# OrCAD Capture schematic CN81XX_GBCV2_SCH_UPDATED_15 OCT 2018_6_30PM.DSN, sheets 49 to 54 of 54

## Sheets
49 25.BOOT EMMC /SD: size Custom; title: BOOT EMMC/MMC
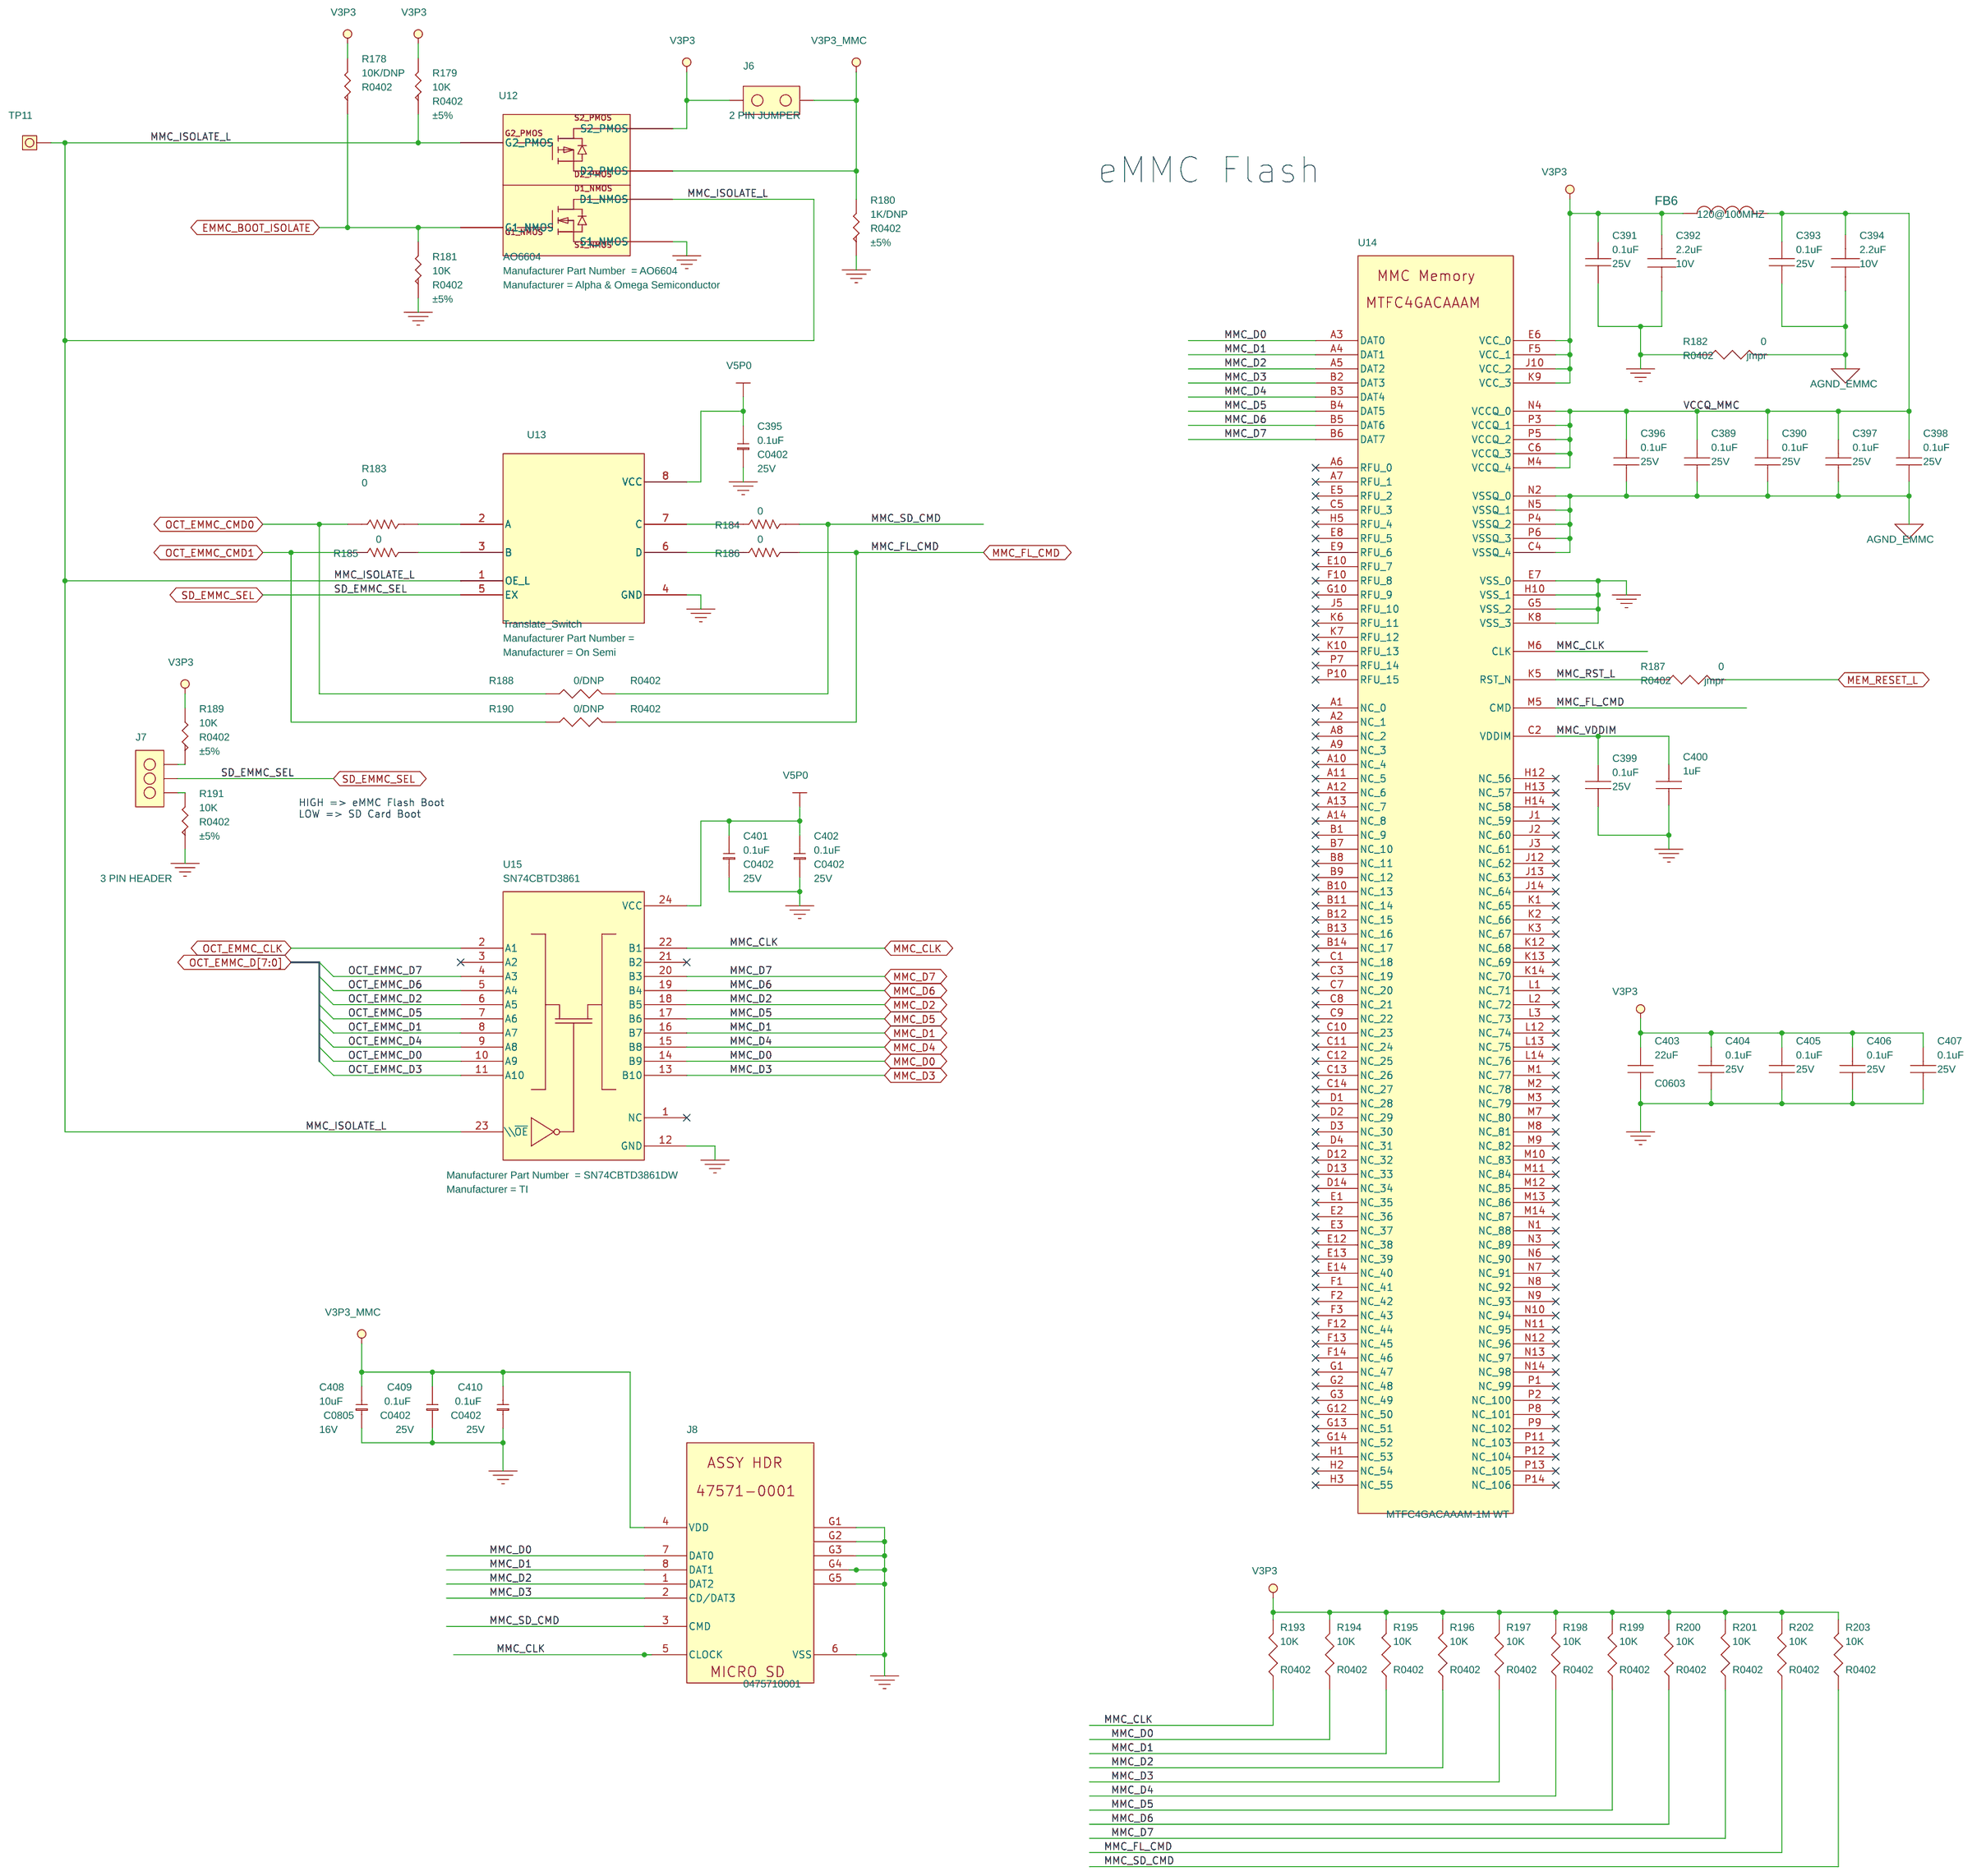
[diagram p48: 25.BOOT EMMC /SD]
50 10.CN81XX DLM3:0, RGMII: size B; title: CN81XX DLM3:0, RGMII
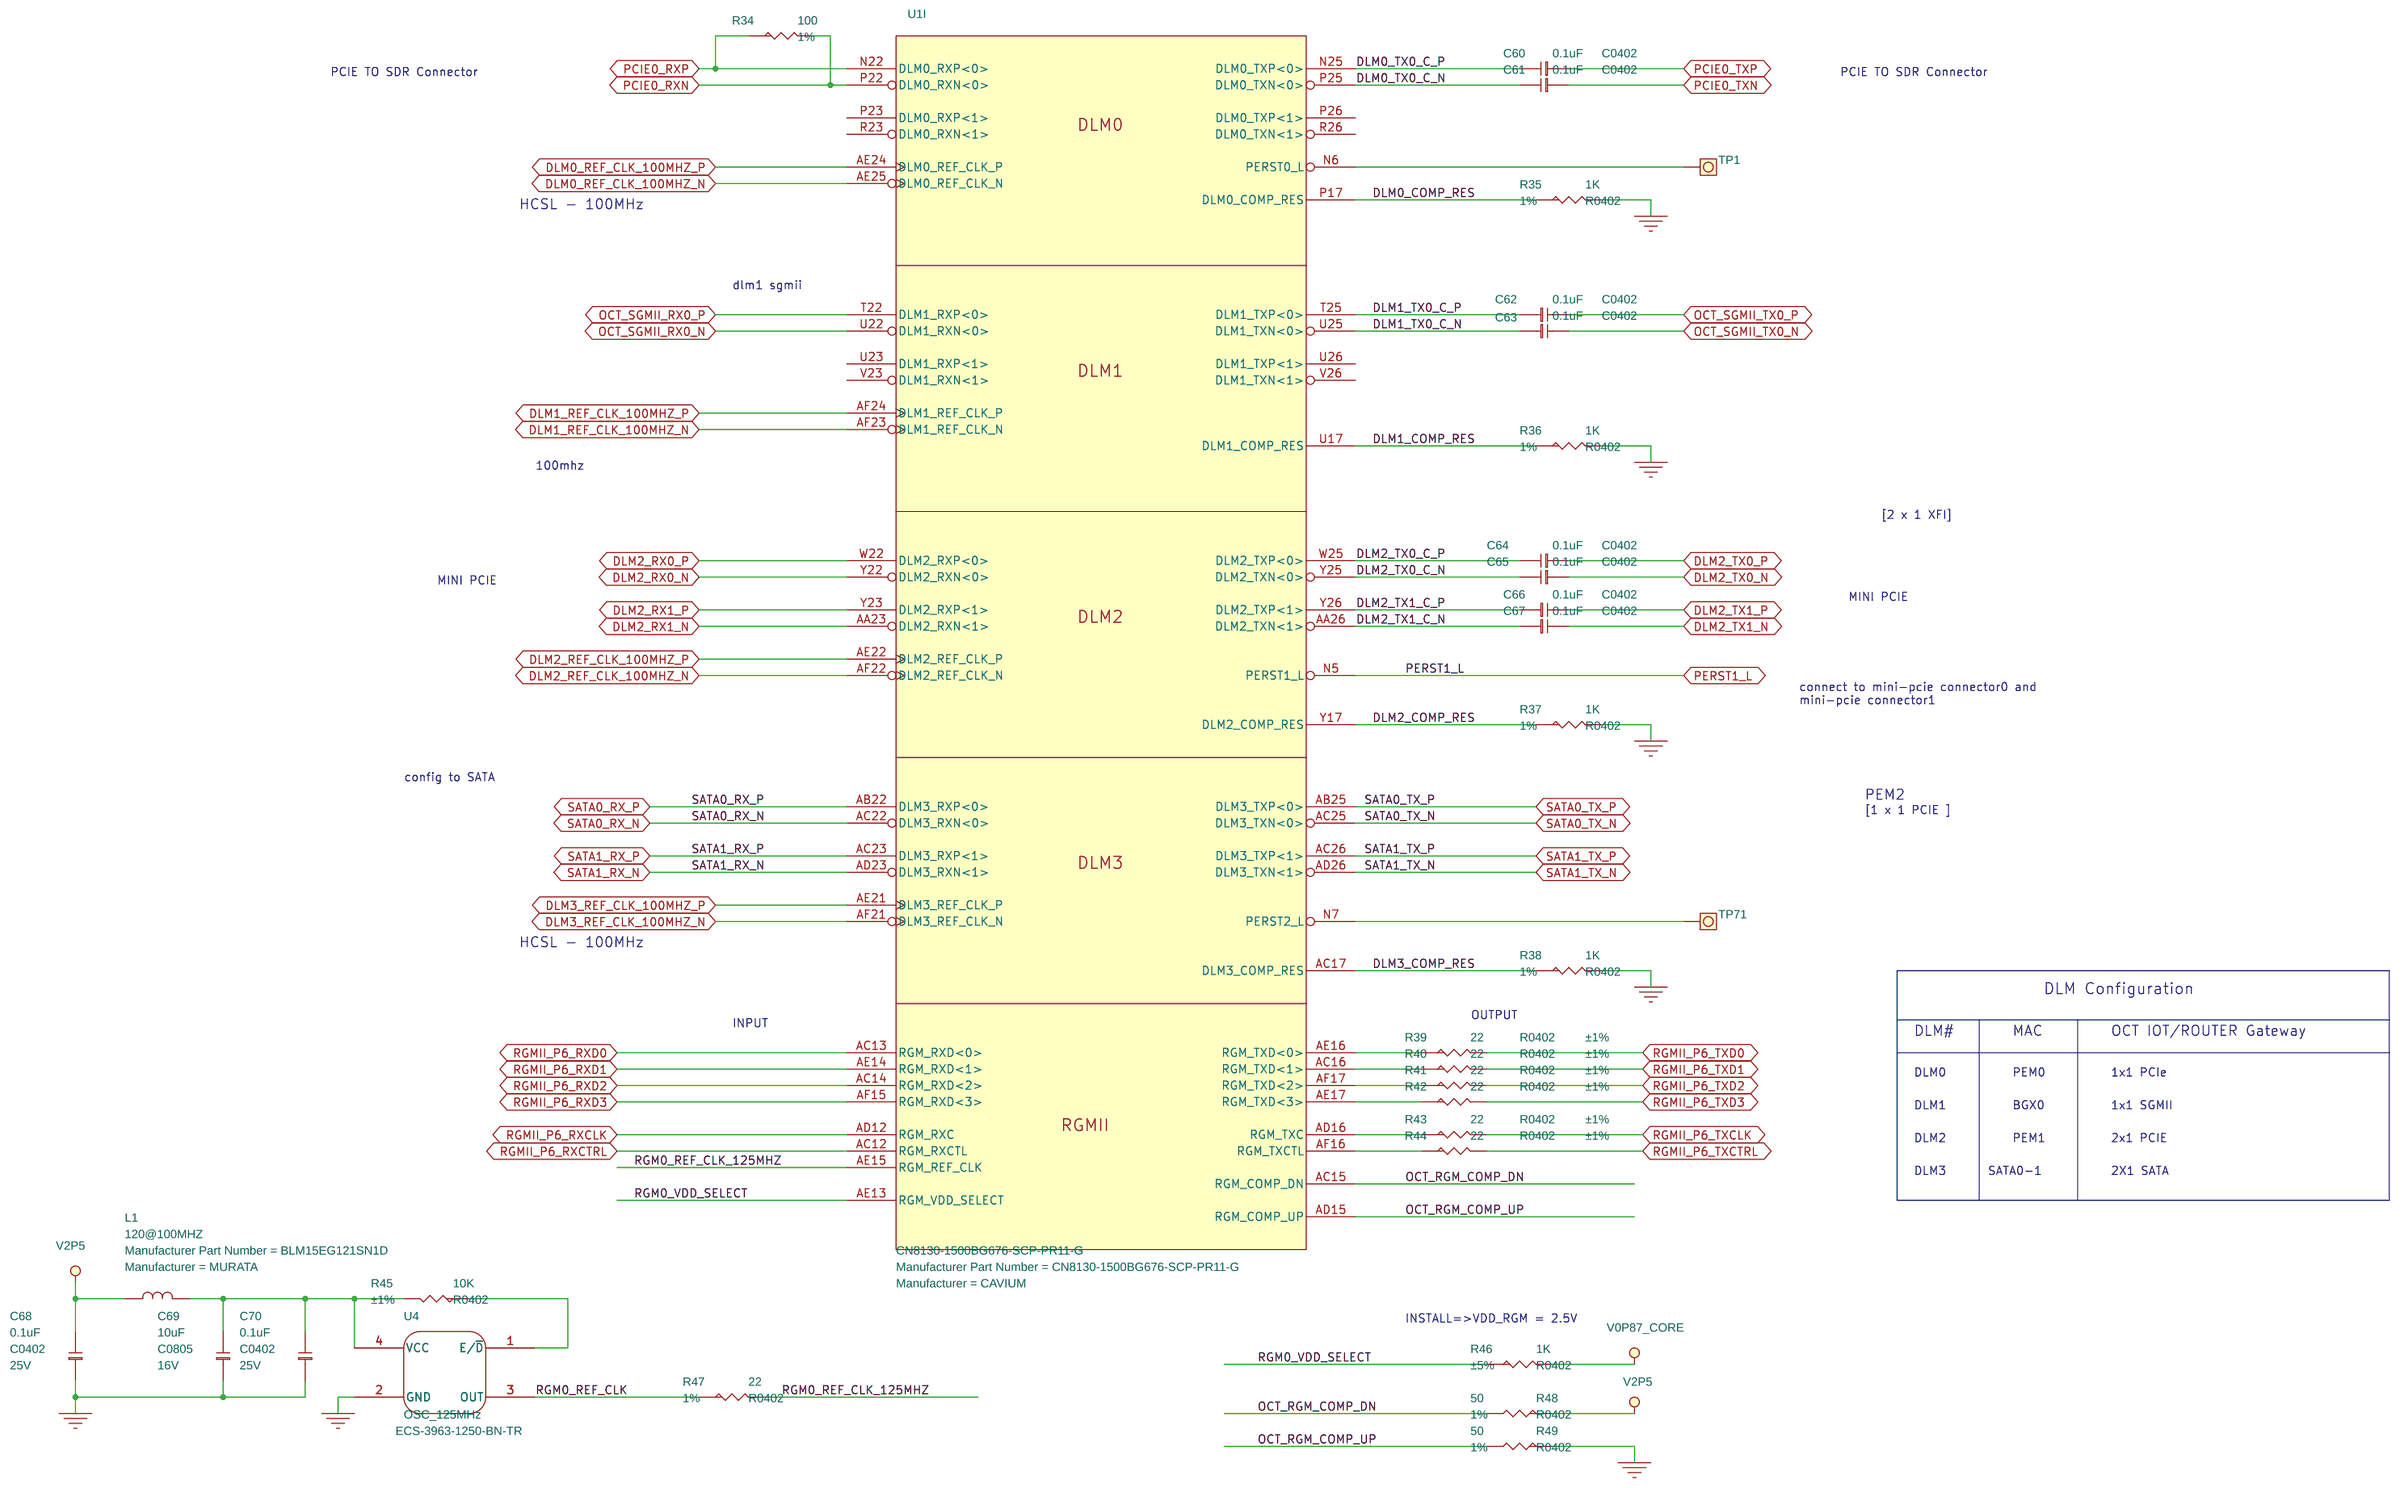
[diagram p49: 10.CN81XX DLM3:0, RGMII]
51 14.CN81XX I/O & MISC VDD: size B; title: CN81XX I/O & MISC VDD
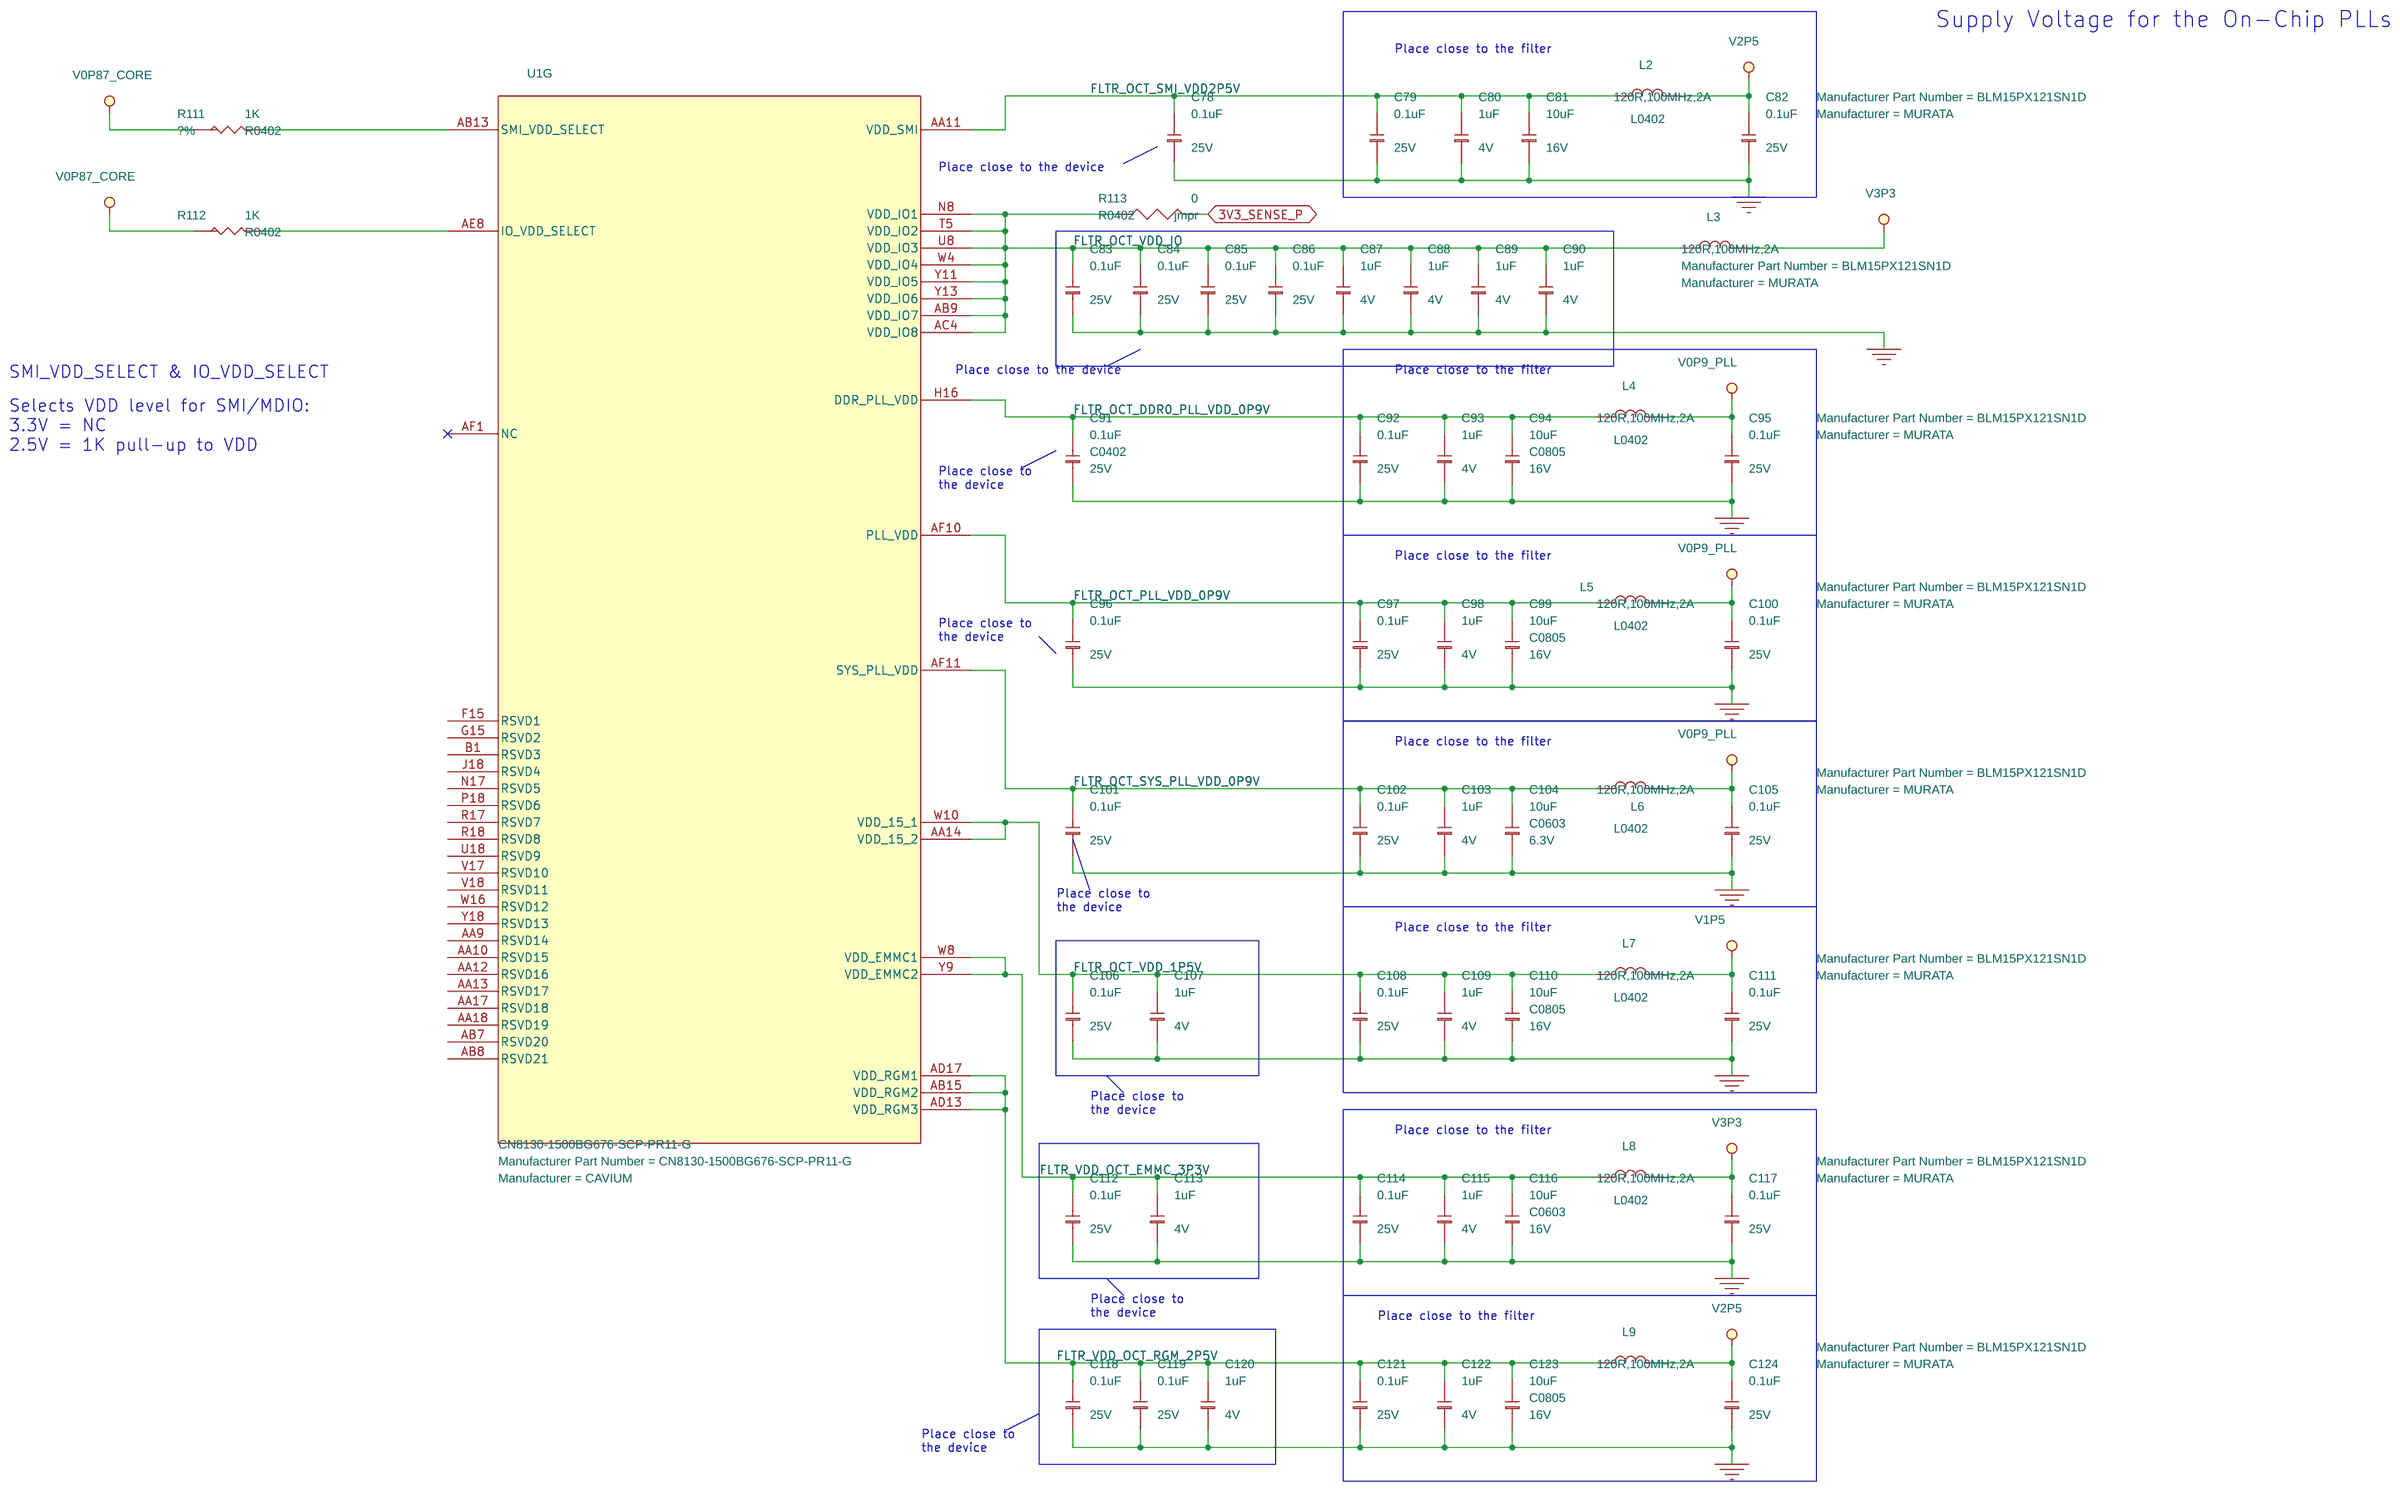
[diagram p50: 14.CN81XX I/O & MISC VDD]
52 31.CONTLR : CPU CORE & 3V3: size B; title: CONTROL:CPU  CORE&3V3
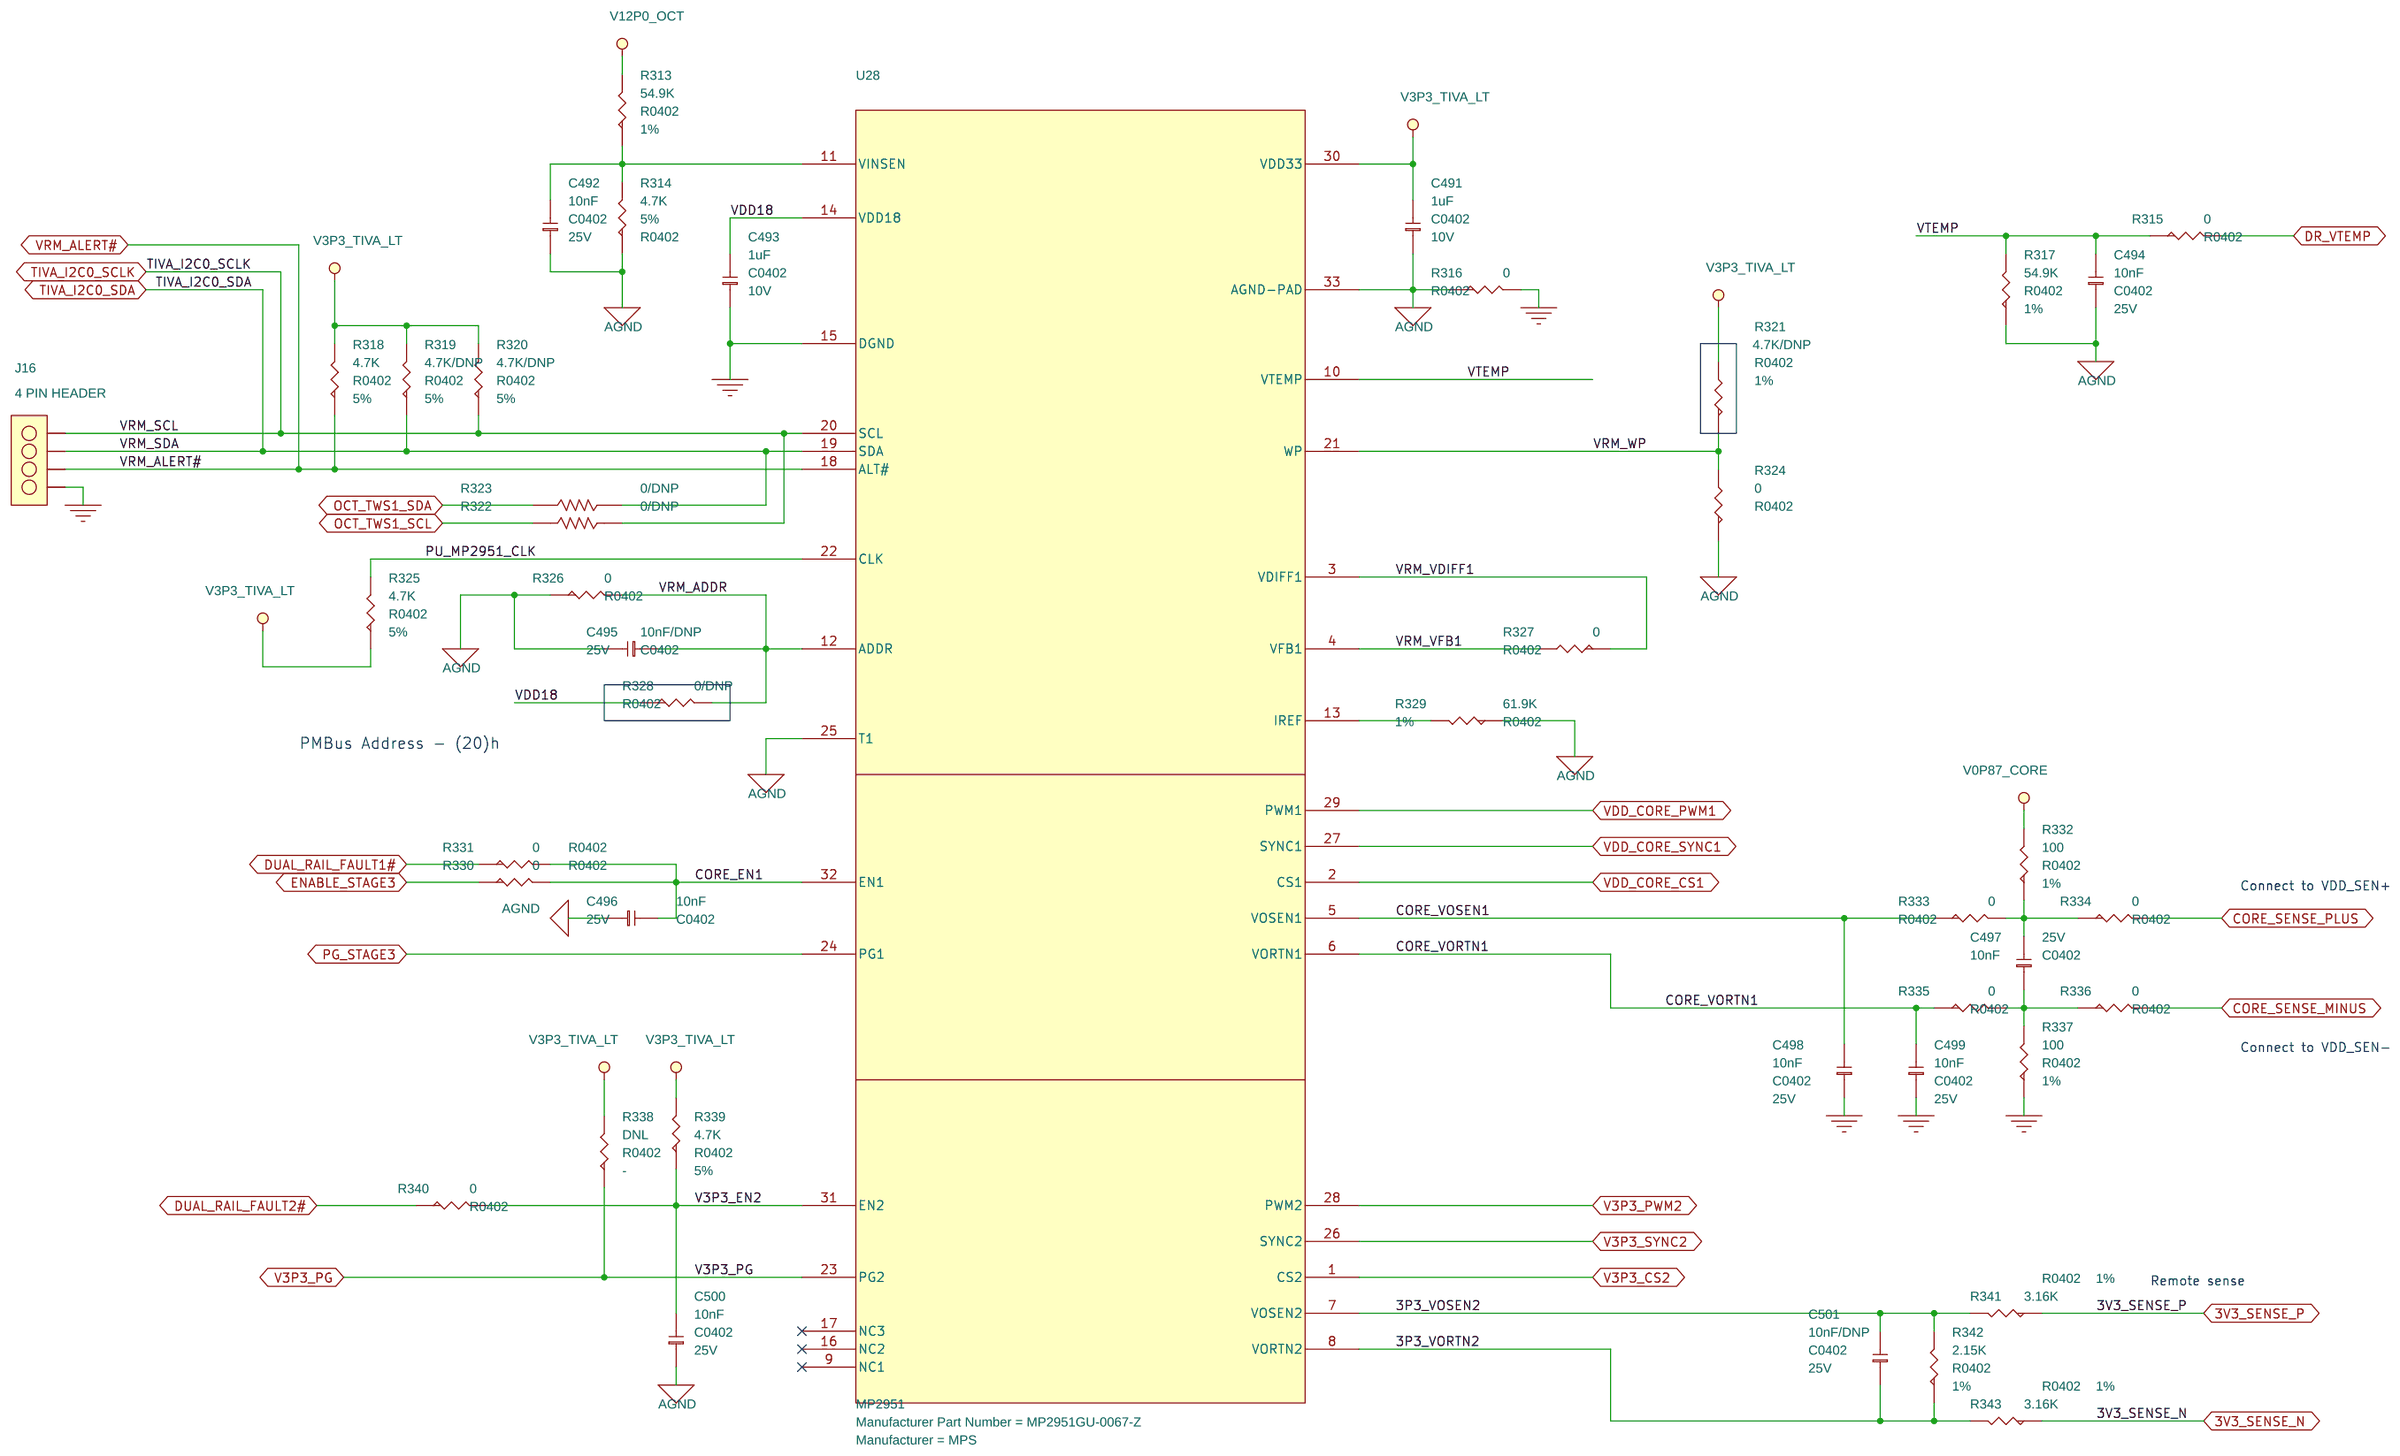
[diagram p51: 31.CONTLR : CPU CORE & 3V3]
53 12.CN81XX MISCELLANEOUS I/O: size B; title: CN81XX MISCELLANEOUS I/O
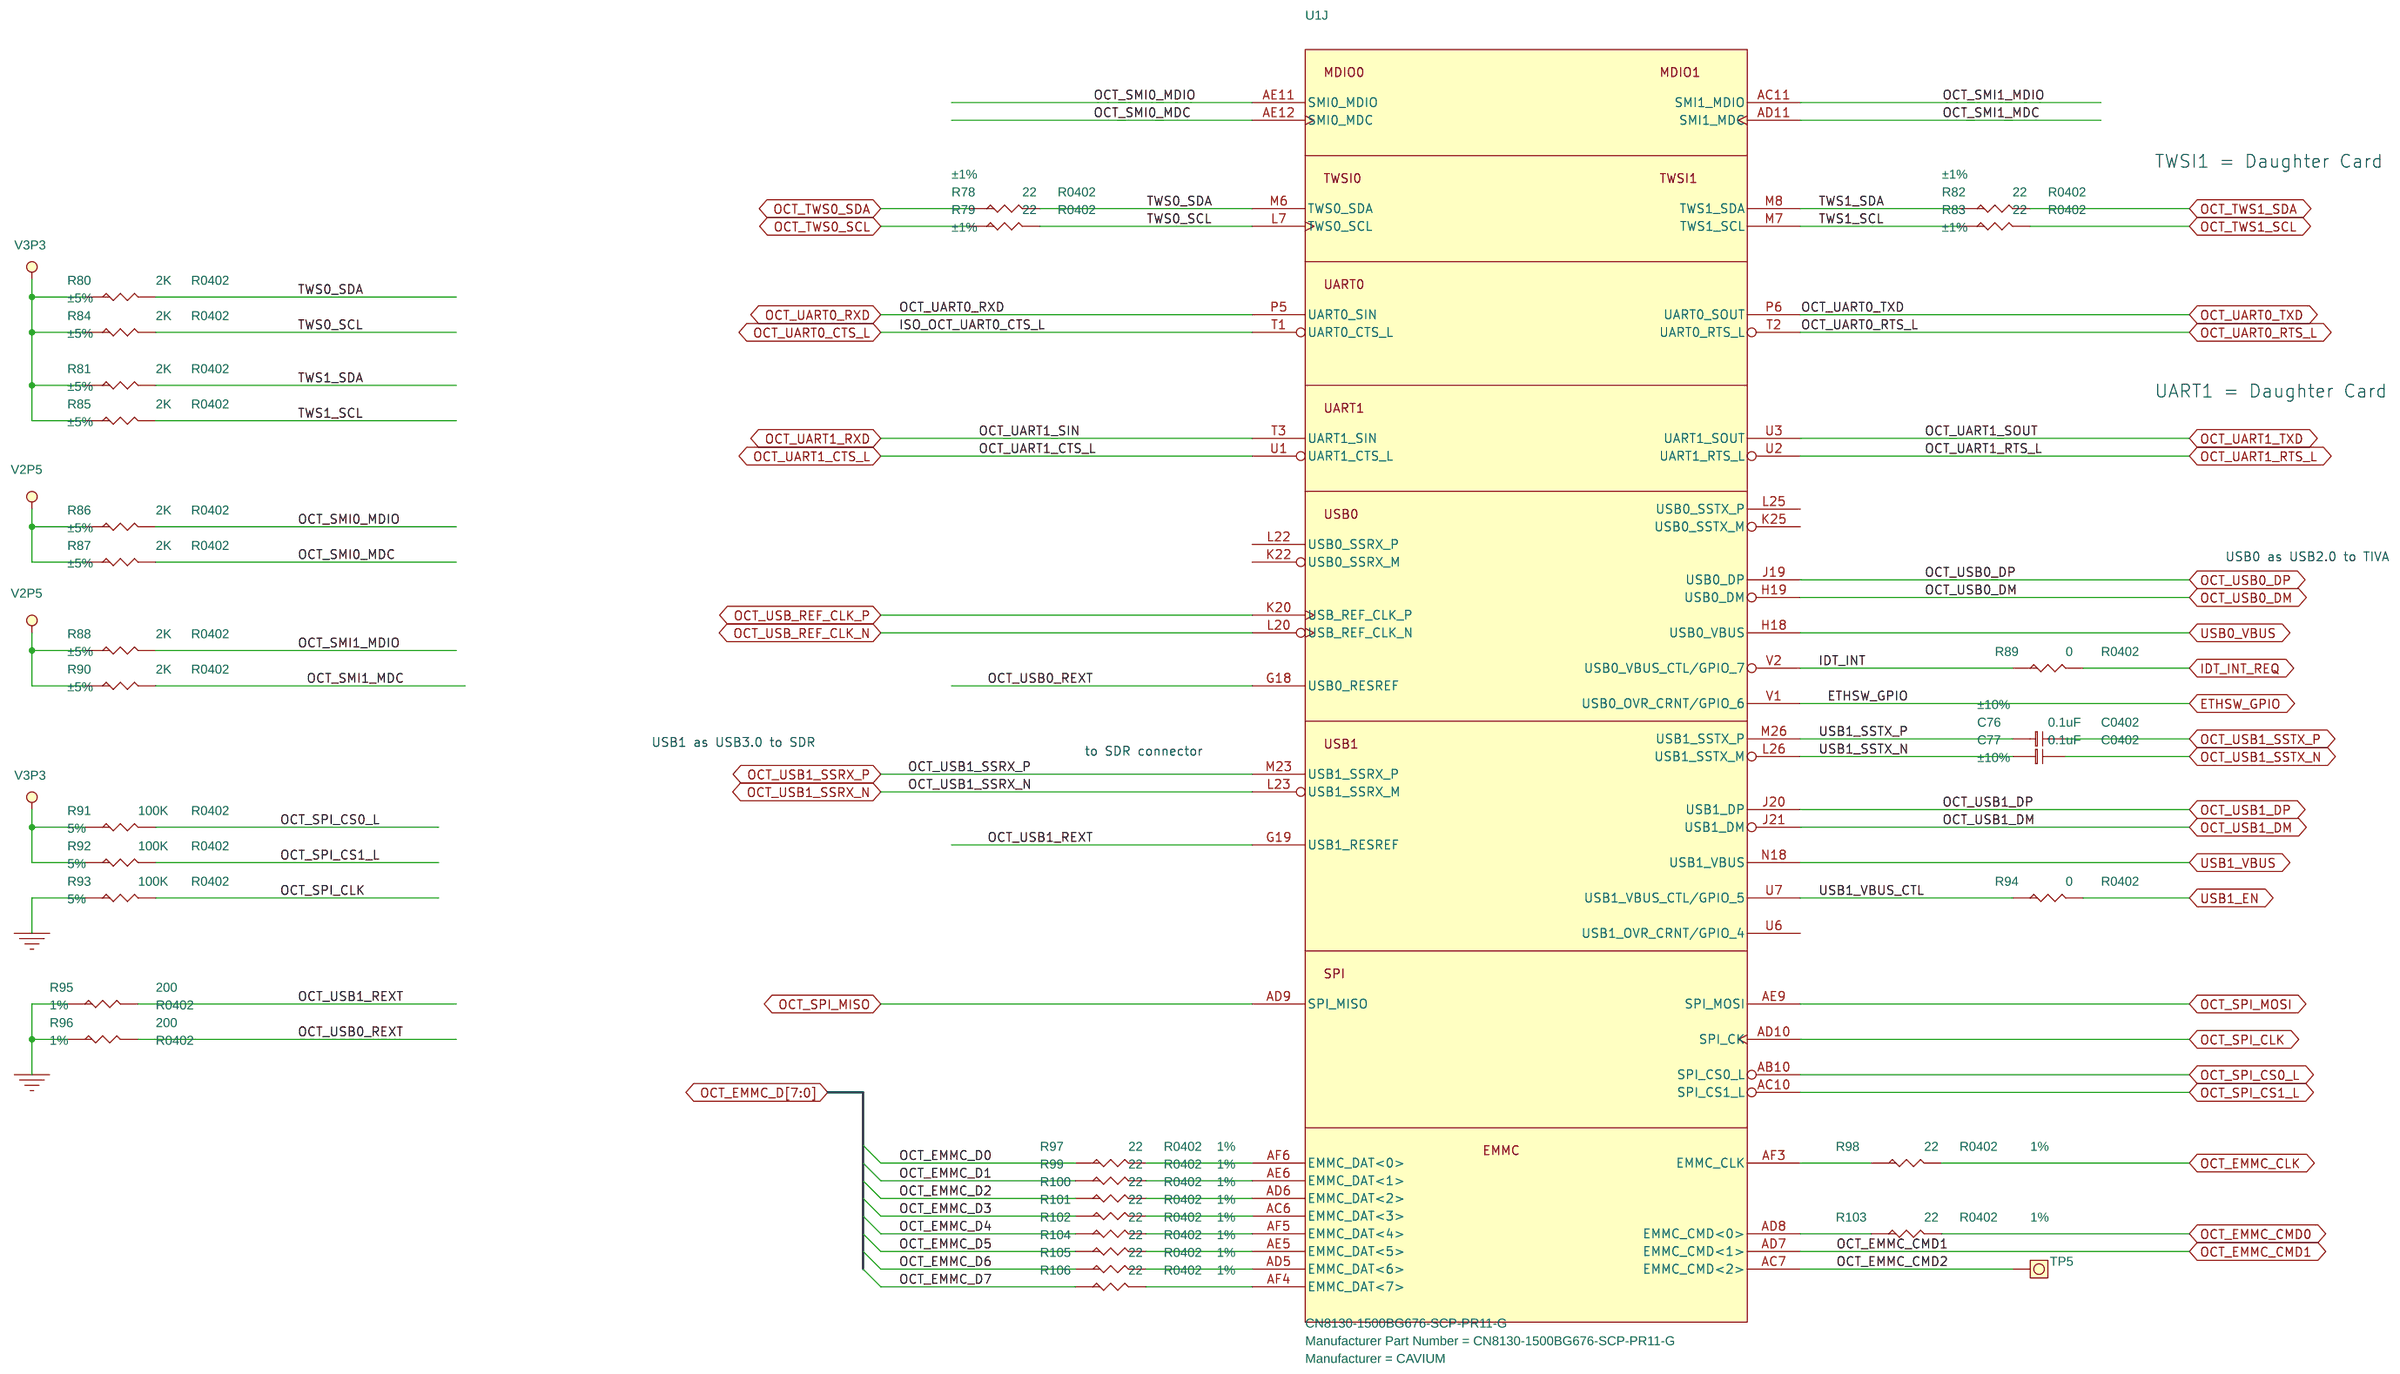
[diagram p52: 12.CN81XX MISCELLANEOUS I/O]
54 32.GATE DRVRS : CORE & 3V3: size B; title: GATE DRVRS
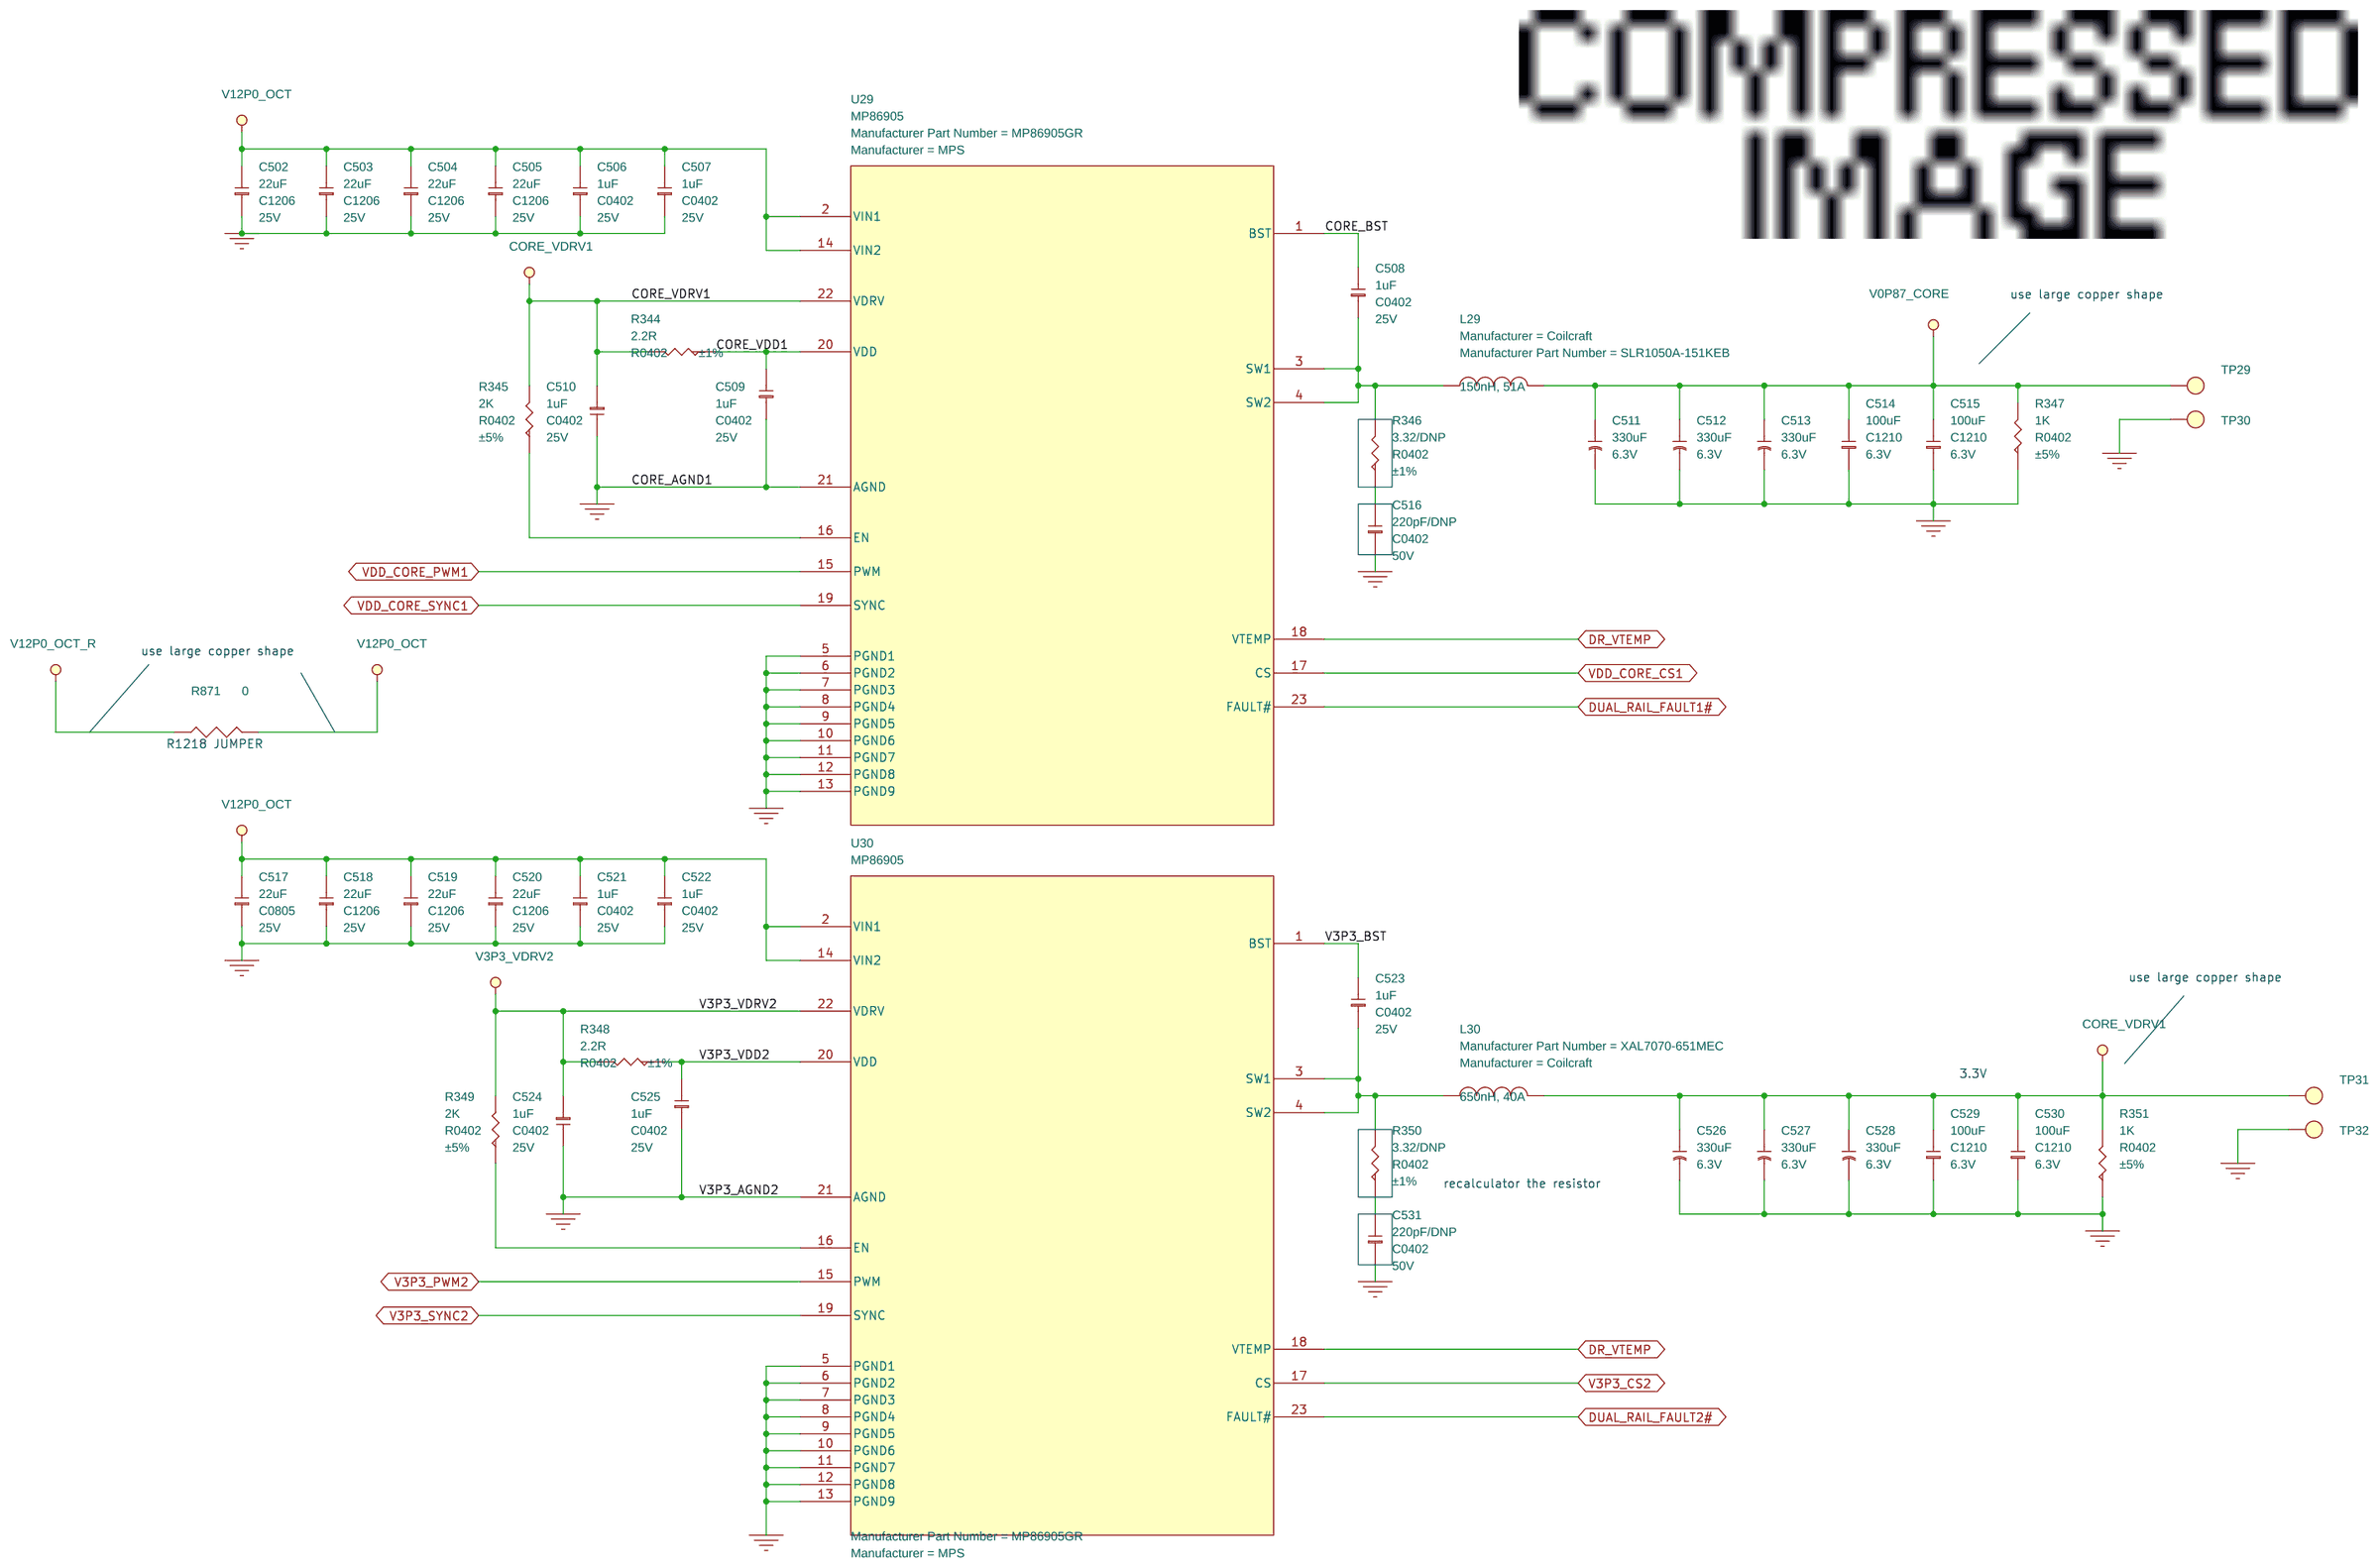
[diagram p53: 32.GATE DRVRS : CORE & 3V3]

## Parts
sheet 10.CN81XX DLM3:0, RGMII
C60  0.1uF  [C0402]
C61  0.1uF  [C0402]
C62  0.1uF  [C0402]
C63  0.1uF  [C0402]
C64  0.1uF  [C0402]
C65  0.1uF  [C0402]
C66  0.1uF  [C0402]
C67  0.1uF  [C0402]
C68  0.1uF  [C0402]
C69  10uF  [C0805]
C70  0.1uF  [C0402]
L1  120@100MHZ  [L0402]
R34  100  [R0402]
R35  1K  [R0402]
R36  1K  [R0402]
R37  1K  [R0402]
R38  1K  [R0402]
R39  22  [R0402]
R40  22  [R0402]
R41  22  [R0402]
R42  22  [R0402]
R43  22  [R0402]
R44  22  [R0402]
R45  10K  [R0402]
R46  1K  [R0402]
R47  22  [R0402]
R48  50  [R0402]
R49  50  [R0402]
TP1  TEST POINT  [TP_SMD]
TP71  TEST POINT  [TP_SMD]
U4  OSC_125MHz  [OSC6SMT_5X3_2]
sheet 12.CN81XX MISCELLANEOUS I/O
C76  0.1uF  [C0402]
C77  0.1uF  [C0402]
R78  22  [R0402]
R79  22  [R0402]
R80  2K  [R0402]
R81  2K  [R0402]
R82  22  [R0402]
R83  22  [R0402]
R84  2K  [R0402]
R85  2K  [R0402]
R86  2K  [R0402]
R87  2K  [R0402]
R88  2K  [R0402]
R89  0  [R0402]
R90  2K  [R0402]
R91  100K  [R0402]
R92  100K  [R0402]
R93  100K  [R0402]
R94  0  [R0402]
R95  200  [R0402]
R96  200  [R0402]
R97  22  [R0402]
R98  22  [R0402]
R99  22  [R0402]
R100  22  [R0402]
R101  22  [R0402]
R102  22  [R0402]
R103  22  [R0402]
R104  22  [R0402]
R105  22  [R0402]
R106  22  [R0402]
TP5  TEST POINT  [TP_SMD]
sheet 13.CN81XX CORE VDD
U1  CN8130-1500BG676-SCP-PR11-G  [BGA-676]  (sections A,B,C,D,E,F,G,H,I,J,K)
sheet 14.CN81XX I/O & MISC VDD
C78  0.1uF  [C0402-BGA]
C79  0.1uF  [C0402-BGA]
C80  1uF  [C0402-BGA]
C81  10uF  [C0805]
C82  0.1uF  [C0402-BGA]
C83  0.1uF  [C0402-BGA]
C84  0.1uF  [C0402-BGA]
C85  0.1uF  [C0402-BGA]
C86  0.1uF  [C0402-BGA]
C87  1uF  [C0402-BGA]
C88  1uF  [C0402-BGA]
C89  1uF  [C0402-BGA]
C90  1uF  [C0402-BGA]
C91  0.1uF  [C0402]
C92  0.1uF  [C0402-BGA]
C93  1uF  [C0402-BGA]
C94  10uF  [C0805]
C95  0.1uF  [C0402-BGA]
C96  0.1uF  [C0402-BGA]
C97  0.1uF  [C0402-BGA]
C98  1uF  [C0402-BGA]
C99  10uF  [C0805]
C100  0.1uF  [C0402-BGA]
C101  0.1uF  [C0402-BGA]
C102  0.1uF  [C0402-BGA]
C103  1uF  [C0402-BGA]
C104  10uF  [C0603]
C105  0.1uF  [C0402-BGA]
C106  0.1uF  [C0402-BGA]
C107  1uF  [C0402-BGA]
C108  0.1uF  [C0402-BGA]
C109  1uF  [C0402-BGA]
C110  10uF  [C0805]
C111  0.1uF  [C0402-BGA]
C112  0.1uF  [C0402-BGA]
C113  1uF  [C0402-BGA]
C114  0.1uF  [C0402-BGA]
C115  1uF  [C0402-BGA]
C116  10uF  [C0603]
C117  0.1uF  [C0402-BGA]
C118  0.1uF  [C0402-BGA]
C119  0.1uF  [C0402-BGA]
C120  1uF  [C0402-BGA]
C121  0.1uF  [C0402-BGA]
C122  1uF  [C0402-BGA]
C123  10uF  [C0805]
C124  0.1uF  [C0402-BGA]
L2  120R,100MHz,2A  [L0402]
L3  120R,100MHz,2A  [L0402]
L4  120R,100MHz,2A  [L0402]
L5  120R,100MHz,2A  [L0402]
L6  120R,100MHz,2A  [L0402]
L7  120R,100MHz,2A  [L0402]
L8  120R,100MHz,2A  [L0402]
L9  120R,100MHz,2A  [L0402]
R111  1K  [R0402]
R112  1K  [R0402]
R113  0  [R0402]
sheet 25.BOOT EMMC /SD
C389  0.1uF  [C0402]
C390  0.1uF  [C0402]
C391  0.1uF  [C0402]
C392  2.2uF  [C0402]
C393  0.1uF  [C0402]
C394  2.2uF  [C0402]
C395  0.1uF  [C0402]
C396  0.1uF  [C0402]
C397  0.1uF  [C0402]
C398  0.1uF  [C0402]
C399  0.1uF  [C0402]
C400  1uF  [C0402]
C401  0.1uF  [C0402]
C402  0.1uF  [C0402]
C403  22uF  [C0603]
C404  0.1uF  [C0402]
C405  0.1uF  [C0402]
C406  0.1uF  [C0402]
C407  0.1uF  [C0402]
C408  10uF  [C0805]
C409  0.1uF  [C0402]
C410  0.1uF  [C0402]
FB6  120@100MHZ  [L0402]
J6  2 PIN JUMPER  [HDR_1X2]
J7  3 PIN HEADER  [HDR_1X3]
J8  0475710001  [MOLEX_SD-47571-0001]
R178  10K/DNP  [R0402]
R179  10K  [R0402]
R180  1K/DNP  [R0402]
R181  10K  [R0402]
R182  0  [R0402]
R183  0  [R0402]
R184  0  [R0402]
R185  0  [R0402]
R186  0  [R0402]
R187  0  [R0402]
R188  0/DNP  [R0402]
R189  10K  [R0402]
R190  0/DNP  [R0402]
R191  10K  [R0402]
R193  10K  [R0402]
R194  10K  [R0402]
R195  10K  [R0402]
R196  10K  [R0402]
R197  10K  [R0402]
R198  10K  [R0402]
R199  10K  [R0402]
R200  10K  [R0402]
R201  10K  [R0402]
R202  10K  [R0402]
R203  10K  [R0402]
TP11  TEST POINT  [TP_SMD]
U12  AO6604  [PG-TSOP-6]
U13  Translate_Switch  [US8_7WBD383USG]
U14  MTFC4GACAAAM-1M WT  [bga153_0o5mm_14x14_mic]
U15  SN74CBTD3861  [SOIC-24]
sheet 31.CONTLR : CPU CORE & 3V3
C491  1uF  [C0402]
C492  10nF  [C0402]
C493  1uF  [C0402]
C494  10nF  [C0402]
C495  10nF/DNP  [C0402]
C496  10nF  [C0402]
C497  10nF  [C0402]
C498  10nF  [C0402]
C499  10nF  [C0402]
C500  10nF  [C0402]
C501  10nF/DNP  [C0402]
J16  4 PIN HEADER  [HDR_1X4]
R313  54.9K  [R0402]
R314  4.7K  [R0402]
R315  0  [R0402]
R316  0  [R0402]
R317  54.9K  [R0402]
R318  4.7K  [R0402]
R319  4.7K/DNP  [R0402]
R320  4.7K/DNP  [R0402]
R321  4.7K/DNP  [R0402]
R322  0/DNP  [R0402]
R323  0/DNP  [R0402]
R324  0  [R0402]
R325  4.7K  [R0402]
R326  0  [R0402]
R327  0  [R0402]
R328  0/DNP  [R0402]
R329  61.9K  [R0402]
R330  0  [R0402]
R331  0  [R0402]
R332  100  [R0402]
R333  0  [R0402]
R334  0  [R0402]
R335  0  [R0402]
R336  0  [R0402]
R337  100  [R0402]
R338  DNL  [R0402]
R339  4.7K  [R0402]
R340  0  [R0402]
R341  3.16K  [R0402]
R342  2.15K  [R0402]
R343  3.16K  [R0402]
U28  MP2951  [QFN32_MP2951]
sheet 32.GATE DRVRS : CORE & 3V3
C502  22uF  [C1206]
C503  22uF  [C1206]
C504  22uF  [C1206]
C505  22uF  [C1206]
C506  1uF  [C0402]
C507  1uF  [C0402]
C508  1uF  [C0402]
C509  1uF  [C0402]
C510  1uF  [C0402]
C511  330uF  [CT7343]
C512  330uF  [CT7343]
C513  330uF  [CT7343]
C514  100uF  [C1210]
C515  100uF  [C1210]
C516  220pF/DNP  [C0402]
C517  22uF  [C0805]
C518  22uF  [C1206]
C519  22uF  [C1206]
C520  22uF  [C1206]
C521  1uF  [C0402]
C522  1uF  [C0402]
C523  1uF  [C0402]
C524  1uF  [C0402]
C525  1uF  [C0402]
C526  330uF  [CT7343]
C527  330uF  [CT7343]
C528  330uF  [CT7343]
C529  100uF  [C1210]
C530  100uF  [C1210]
C531  220pF/DNP  [C0402]
L29  150nH, 51A  [IND_SLR1050A]
L30  650nH, 40A  [IND_XAL7070]
R344  2.2R  [R0402]
R345  2K  [R0402]
R346  3.32/DNP  [R0402]
R347  1K  [R0402]
R348  2.2R  [R0402]
R349  2K  [R0402]
R350  3.32/DNP  [R0402]
R351  1K  [R0402]
R871  0  [R1812]
TP29  TP_PWR  [TP_TH_40MIL]
TP30  TP_PWR  [TP_TH_40MIL]
TP31  TP_PWR  [TP_TH_40MIL]
TP32  TP_PWR  [TP_TH_40MIL]
U29  MP86905  [FCTQFN23L-4X4MM]
U30  MP86905  [FCTQFN23L-4X4MM]

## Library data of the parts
C60-C68 C70 C76-C79 C82-C86 C91 C92 C95-C97 C100-C102 C105 C106 C108 C111 C112 C114 C117-C119 C121 C124 = CAP_NONPOL: CAP CER 0.1UF 25V 10% X7R 0402; MFG: Murata; MFG_PN: GRM155R71C104KA88D; Manufacturer: MURATA; Manufacturer Part Number: GRM155R71C104KA88D; Tolerance: ±10%; Voltage: 25V
C69 C81 C94 C99 C110 C123 = CAP_NONPOL: CAP CER 10UF 16V X5R 0805; MFG: MURATA; MFG_PN: GRM21BR61C106KE15K; Manufacturer: MURATA; Manufacturer Part Number: GRM21BR61C106KE15K; Tolerance: ±10%; Voltage: 16V
L1 = FERRITE_BEAD: FERRITE BEAD 120 OHM 0402 1LN; Manufacturer: MURATA; Manufacturer Part Number: BLM15EG121SN1D
R34 R332 R337 = RESISTOR_1: RES SMD 100 OHM 1% 1/16W 0402; Manufacturer: VISHAY DALE; Manufacturer Part Number: CRCW0402100RFKED; Tolerance: 1%; Wattage: 1/16W
R35-R38 = RESISTOR_1: RES SMD 1K OHM 1% 1/10W 0402; MFG: Panasonic; MFG_PN: ERJ-2RKF1001X; Manufacturer: Panasonic; Manufacturer Part Number: ERJ-2RKF1001X; Tolerance: 1%; Wattage: 1/10W
R39-R44 R78 R79 R82 R83 = RESISTOR_1: RES SMD 22 OHM 1% 1/16W 0402; MFG: VISHAY DALE; MFG_PN: CRCW040222R0FKED; Manufacturer: VISHAY DALE; Manufacturer Part Number: CRCW040222R0FKED; Tolerance: ±1%; Wattage: 1/16W
R45 = RESISTOR_1: RES SMD 10K OHM 1% 1/16W 0402; MFG: VISHAY DALE; MFG_PN: CRCW040210K0JNED; Manufacturer: VISHAY DALE; Manufacturer Part Number: CRCW040210K0FKED; Tolerance: ±1%; Wattage: 1/16W
R46 = RESISTOR_1: RES SMD 1K OHM 5% 1/16W 0402; MFG: VISHAY DALE; MFG_PN: CRCW04021K00JNED; Manufacturer: VISHAY DALE; Manufacturer Part Number: CRCW04021K00JNED; Tolerance: ±5%; Wattage: 1/10W
R47 = RESISTOR_4: RES SMD 22 OHM 1% 1/16W 0402; MFG: VISHAY DALE; MFG_PN: CRCW040222R0FKED; Manufacturer: VISHAY DALE; Manufacturer Part Number: CRCW040222R0FKED; Tolerance: 1%; Wattage: 1/16W
R48 R49 = RESISTOR_1: RES SMD 50 OHM 1% 1/16W 0402; Manufacturer: YAGEO; Manufacturer Part Number: RC0402FR-0750RL; Tolerance: 1%; Wattage: 1/16W
TP1 TP5 TP11 TP71 = TEST_POINT
U4 = SM7745DV-125.0M: OSC XO 125.000MHZ CMOS SMD 50PPM; Manufacturer: ECS Inc.; Manufacturer Part Number: ECS-3963-1250-BN-TR
R80 R81 R84-R88 R90 = RESISTOR_1: RES SMD 2K OHM 5% 1/10W 0402; MFG: Panasonic; MFG_PN: ERJ-2GEJ202X; Manufacturer: Panasonic; Manufacturer Part Number: ERJ-2GEJ202X; Tolerance: ±5%; Wattage: 1/16W
R89 R94 = RESISTOR_1: RES SMD 0.0OHM JUMPER 1/16W 0402; MFG: Panasonic; MFG_PN: ERJ-2GE0R00X; Manufacturer: VISHAY DALE; Manufacturer Part Number: CRCW04020000Z0ED; Wattage: 1/16W
R91-R93 = RESISTOR_1: RES SMD 100K OHM 5% 1/16W 0402; Manufacturer: VISHAY DALE; Manufacturer Part Number: CRCW0402100KJNED; Tolerance: 5%; Wattage: 1/16W
R95 R96 = RESISTOR_1: RES SMD 200 OHM 1% 1/16W 0402; Manufacturer: VISHAY DALE; Manufacturer Part Number: CRCW0402200RFKED; Tolerance: 1%; Wattage: 1/16W
R97-R106 = RESISTOR_1: RES SMD 22 OHM 1% 1/16W 0402; MFG: VISHAY DALE; MFG_PN: CRCW040222R0FKED; Manufacturer: VISHAY DALE; Manufacturer Part Number: CRCW040222R0FKED; Tolerance: 1%; Wattage: 1/16W
U1 = CN81XX_List_V0_3.60: Manufacturer: CAVIUM
C80 C87-C90 C93 C98 C103 C107 C109 C113 C115 C120 C122 = CAP_NONPOL: CAP CER 1UF 4V X7R 0402; MFG: Murata; MFG_PN: GRM155R70G105KA12D; Manufacturer: MURATA; Manufacturer Part Number: GRM155R70G105KA12D; Tolerance: ±10%; Voltage: 4V
C104 = CAP_NONPOL: CAP CER 10UF 6.3V X5R 0603; MFG: MURATA; MFG_PN: GRM188R60J106KE47D; Manufacturer: MURATA; Manufacturer Part Number: GRM188R60J106KE47D; Tolerance: ±10%; Voltage: 6.3V
C116 = CAP_NONPOL: CAP CER 10UF 16V X5R 0603; MFG: MURATA; MFG_PN: GRM188R60J106ME47D; Manufacturer: MURATA; Manufacturer Part Number: GRM188R60J106ME47D; Tolerance: ±10%; Voltage: 16V
L2-L9 = FERRITE_BEAD: FERRITE BEAD 120 OHM 0402 1LN; Manufacturer: MURATA; Manufacturer Part Number: BLM15PX121SN1D
R111 = RESISTOR_1: RES SMD 1K OHM 5% 1/16W 0402; MFG: VISHAY DALE; MFG_PN: CRCW04021K00JNED; Manufacturer: VISHAY DALE; Manufacturer Part Number: CRCW04021K00JNED; Tolerance: ?%; Wattage: 1/10W
R112 = RESISTOR_1: RES SMD 1K OHM 5% 1/16W 0402; MFG: VISHAY DALE; MFG_PN: CRCW04021K00JNED; Manufacturer: VISHAY DALE; Manufacturer Part Number: CRCW04021K00JNED; Tolerance: 1%; Wattage: 1/16W
R113 R182 R187 = res_0402_0R0_0.1W_Jmpr_smd: RES SMD 0.0OHM JUMPER 1/16W 0402; Manufacturer: VISHAY DALE; Manufacturer Part Number: CRCW04020000Z0ED; Tolerance: jmpr
C389-C391 C393 C396-C399 C404-C407 = cap_0402_0.1uF_16V_10%_X7R: CAP CER 0.1UF 25V 10% X7R 0402; Manufacturer: MURATA; Manufacturer Part Number: GRM155R71C104KA88D; Voltage: 25V
C392 C394 = cap_0402_2.2uF_25V_10%_X5R_smd: CAP CER 2.2UF 10V X5R 0402; Manufacturer: TDK; Manufacturer Part Number: C1005X5R1A225K050BC; Voltage: 10V
C395 C401 C402 = CAP_NONPOL: CAP CER 0.1UF 25V 10% X7R 0402; Manufacturer: MURATA; Manufacturer Part Number: GRM155R71C104KA88D; Tolerance: ±10%; Voltage: 25V
C400 = cap_0402_1uF_10V_10%_X5R_smd
C403 = cap_0603_22uF_6V3_10%_X5R
C408 = CAP_NONPOL: CAP CER 10UF 16V X5R 0805; Manufacturer: MURATA; Manufacturer PN: GRM21BR61C106KE15K; Manufacturer Part Number: GRM21BR61C106KE15K; Tolerance: ±10%; Voltage: 16V
C409 C410 = CAP_NONPOL: CAP CER 0.1UF 25V 10% X7R 0402; Manufacturer: MURATA; Manufacturer PN: GRM155R71C104KA88D; Manufacturer Part Number: GRM155R71C104KA88D; Tolerance: ±10%; Voltage: 25V
FB6 = fer_120_1.5A_BLM15EG121SN1D_sm: Manufacturer: MURATA; Manufacturer Part Number: BLM15EG121SN1D
J6 = 2_PIN_HEADER: 2 Positions Header, Unshrouded, Breakaway Connector 0.100" (2.54mm) Through Hole Gold; Manufacturer: TE Connectivity; Manufacturer Part Number: 5-146280-2
J7 = 3_PIN_HEADER: CONN HEADR BRKWAY .100 3POS STR; Manufacturer: TE Connectivity; Manufacturer Part Number: 5-146280-3
J8 = Assy_hdr_0.30mm_9P_smd: CONN MICRO SD CARD PUSH-PULL R/A; Manufacturer: Molex Inc
R178 R179 R181 R189 R191 = RESISTOR_1: RES SMD 10K OHM 5% 1/16W 0402; Manufacturer: VISHAY DALE; Manufacturer Part Number: CRCW040210K0JNED; Tolerance: ±5%; Wattage: 1/16W
R180 R347 R351 = RESISTOR_1: RES SMD 1K OHM 5% 1/16W 0402; Manufacturer: VISHAY DALE; Manufacturer Part Number: CRCW04021K00JNED; Tolerance: ±5%; Wattage: 1/16W
R183-R186 R322 R323 = RES_0: RES SMD 0.0OHM JUMPER 1/16W 0402; Assembly Option: LOAD; Manufacturer: VISHAY DALE; Manufacturer Part Number: CRCW04020000Z0ED; PART_NUMBER: PAC_RES_02050
R188 R190 = R: RES SMD 0.0OHM JUMPER 1/16W 0402; Manufacturer: VISHAY DALE; Manufacturer Part Number: CRCW04020000Z0ED; PART_NUMBER: ERJ-2RKF1000X; Power_Rating: 100mW
R193-R203 = res_0402_10K0_0.063W_1%_smd
U12 = BSL215C: MOSFET N/P-CH 20V 6-TSOP; Manufacturer: Alpha & Omega Semiconductor
U13 = Translate_Switch: IC BUS SWITCH 1X1 US8; Manufacturer: On Semi
U14 = eMMC_4G_153BGA_MTFC4GACAAAM: Manufacturer: Micron
U15 = SN74CBTD3861: Manufacturer: TI; Manufacturer Part Number: SN74CBTD3861DW; Manufacturer Part Number : SN74CBTD3861DW
C491 C493 = CAP_NONPOL: CAP-1.0UF,10%,10V,X5R,0402; Manufacturer: MURATA; Manufacturer Part Number: GRM155R61A105KE15D; Tolerance: ±10%; Voltage: 10V
C492 C494-C501 = CAP_NONPOL: CAP CER 10000PF 25V X7R 0402; Manufacturer: MURATA; Manufacturer Part Number: GRM155R71E103KA01D; Tolerance: ±10%; Voltage: 25V
J16 = 4_PIN_HEADER: CONN HEADR BRKWAY .100 4POS STR; Manufacturer: TE Connectivity; Manufacturer Part Number: 5-146280-4
R313 R317 = RESISTOR_1: RES-54.9K,1%,1/16W,0402; Manufacturer: VISHAY DALE; Manufacturer Part Number: CRCW040254K9FKED; Tolerance: 1%; Wattage: 1/16W
R314 R318 R319 R325 R339 = RESISTOR_1: RES SMD 4.99K OHM 1% 1/16W 0402; Manufacturer: Panasonic; Manufacturer Part Number: ERJ-2GEJ472X; Tolerance: 5%; Wattage: 1/16W
R315 R316 R324 R326-R328 R330 R331 R333-R336 R340 = RESISTOR_1: RES SMD 0.0OHM JUMPER 1/16W 0402; Manufacturer: VISHAY DALE; Manufacturer Part Number: CRCW04020000Z0ED; Wattage: 1/16W
R320 = RESISTOR_1: RES 4.7K OHM 1/10W 5% 0402 SMD; Manufacturer: Panasonic; Manufacturer Part Number: ERJ-2GEJ472X; Tolerance: 5%; Wattage: 1/16W
R321 = RESISTOR_1: RES SMD 4.99K OHM 1% 1/16W 0402; Manufacturer: Panasonic; Manufacturer Part Number: ERJ-2GEJ472X; Tolerance: 1%; Wattage: 1/16W
R329 = RESISTOR_1: RES-61.9K,1%,1/16W,0402; Manufacturer: VISHAY DALE; Manufacturer Part Number: CRCW040261K9FKED; Tolerance: 1%; Wattage: 1/16W
R338 = RESISTOR_1: Wattage: 1/16W
R341 R343 = RESISTOR_1: RES SMD 3.16K OHM 1% 1/16W 0402; Manufacturer: Yageo; Manufacturer Part Number: RC0402FR-073K16L; Tolerance: 1%; Wattage: 1/16W
R342 = RESISTOR_1: RES SMD 2.15K OHM 1% 1/16W 0402; Manufacturer: VISHAY DALE; Manufacturer Part Number: CRCW04022K15FKED; Tolerance: 1%; Wattage: 1/16W
U28 = MP2951: Dual Phase/Dual Rail Digital POL Controller; Manufacturer: MPS; Manufacturer Part Number: MP2951GU-0067-Z
C502-C505 C518-C520 = CAP_NONPOL: CAP CER 22UF 25V X5R 1206; Manufacturer: MURATA; Manufacturer Part Number: GRM31CR61E226KE15L; Tolerance: 10%; Voltage: 25V
C506-C510 C521-C525 = CAP_NONPOL: CAP CER 1UF 25V 10% X5R 0402; Manufacturer: MURATA; Manufacturer Part Number: GRM155R61E105KA12J; Tolerance: ±10%; Voltage: 25V
C511-C513 C526-C528 = CAP_POL_1: CAP TANT POLY 330UF 6.3V 2917; Manufacturer: Panasonic; Manufacturer Part Number: 6TPF330M9L; Voltage: 6.3V
C514 C515 C529 C530 = CAP_NONPOL: CAP-100UF,20%,20%,6.30V,X5R,1210; Manufacturer: MURATA; Manufacturer Part Number: GRM32ER60J107ME20K; Tolerance: ±20%; Voltage: 6.3V
C516 C531 = CAP_NONPOL: CAP CER 220PF 50V NP0 0402; Manufacturer: KEMET; Manufacturer Part Number: C0402C221J5GACTU; Tolerance: 5%; Voltage: 50V
C517 = CAP_NONPOL: CAP CER 22UF 25V X5R 0805; Manufacturer: MURATA; Manufacturer Part Number: GRM21BR61E226ME44L; Tolerance: 10%; Voltage: 25V
L29 = INDUCTOR: FIXED IND 150NH 51A 0.39 mOHM; Manufacturer: Coilcraft; Manufacturer Part Number: SLR1050A-151KEB
L30 = INDUCTOR: FIXED IND 650NH 40A 1.7mOHM SMD; Manufacturer: Coilcraft; Manufacturer Part Number: XAL7070-651MEC
R344 R348 = RESISTOR_1: RES- 2.2 OHM 1/5W 1% 0402 SMD; Manufacturer: VISHAY DALE; Manufacturer Part Number: CRCW04022R20FKEDHP; Tolerance: ±1%; Wattage: 1/8W
R345 R349 = RESISTOR_1: RES SMD 2K OHM 5% 1/10W 0402; Manufacturer: Panasonic; Manufacturer Part Number: ERJ-2GEJ202X; Tolerance: ±5%; Wattage: 1/16W
R346 = RESISTOR_1: RES SMD 3.32 OHM 1% 1/16W 0402; Manufacturer: yageo; Manufacturer Part Number: CRCW04023R32FKED; Tolerance: ±1%; Wattage: 1/16W
R350 = RESISTOR_1: RES SMD 3.32 OHM 1% 1/16W 0402; Manufacturer: VISHAY DALE; Manufacturer Part Number: CRCW04023R32FKED; Tolerance: ±1%; Wattage: 1/16W
R871 = R: RES SMD 0 OHM 1W 1812 WIDE; Manufacturer: Vishay Dale; Manufacturer Part Number: RCL12180000Z0EK
TP29-TP32 = T_POINT_R
U29 U30 = MP86905: Intelli-PhaseTM Solution in 4x4mm QFN; Manufacturer: MPS; Manufacturer Part Number: MP86905GR

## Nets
3V3_SENSE_N: R343.1 ; also on sheet 15
3V3_SENSE_P: R113.1 R341.1
AGND: C491.2 C492.2 C494.2 C495.1 C496.2 C500.2 R314.1 R316.1 R317.1 R324.1 R326.1 R329.1 U28.25(T1) U28.33(AGND-PAD)
AGND_EMMC: C389.2 C390.2 C393.1 C394.2 C396.2 C397.2 C398.2 R182.1 U14.C4(VSSQ_4) U14.N2(VSSQ_0) U14.N5(VSSQ_1) U14.P4(VSSQ_2) U14.P6(VSSQ_3)
GND: C68.2 C69.2 C70.2 C78.2 C79.2 C80.2 C81.2 C82.2 C83.2 C84.2 C85.2 C86.2 C87.2 C88.2 C89.2 C90.2 C91.2 C92.2 C93.2 C94.2 C95.2 C96.2 C97.2 C98.2 C99.2 C100.2 C101.2 C102.2 C103.2 C104.2 C105.2 C106.2 C107.2 C108.2 C109.2 C110.2 C111.2 C112.2 C113.2 C114.2 C115.2 C116.2 C117.2 C118.2 C119.2 C120.2 C121.2 C122.2 C123.2 C124.2 C391.1 C392.2 C395.2 C399.1 C400.2 C401.2 C402.2 C403.1 C404.2 C405.2 C406.2 C407.2 C408.2 C409.2 C410.2 C493.2 C498.2 C499.2 C502.2 C503.2 C504.2 C505.2 C506.2 C507.2 C509.2 C510.1 C511.2N C512.2N C513.2N C514.2 C515.2 C516.2 C517.2 C518.2 C519.2 C520.2 C521.2 C522.2 C524.1 C525.2 C526.2N C527.2N C528.2N C529.2 C530.2 C531.2 J8.6(VSS) J8.G1 J8.G2 J8.G3 J8.G4 J8.G5 J16.4 R35.2 R36.2 R37.2 R38.2 R49.1 R93.1 R95.1 R96.1 R180.1 R181.1 R182.2 R191.1 R316.2 R337.1 R347.1 R351.1 TP30.1(TP) TP32.1(TP) U4.2(GND) U12.5(S1_NMOS) U13.4(GND) U14.E7(VSS_0) U14.G5(VSS_2) U14.H10(VSS_1) U14.K8(VSS_3) U15.12(GND) U28.15(DGND) U29.5(PGND1) U29.6(PGND2) U29.7(PGND3) U29.8(PGND4) U29.9(PGND5) U29.10(PGND6) U29.11(PGND7) U29.12(PGND8) U29.13(PGND9) U29.21(AGND) U30.5(PGND1) U30.6(PGND2) U30.7(PGND3) U30.8(PGND4) U30.9(PGND5) U30.10(PGND6) U30.11(PGND7) U30.12(PGND8) U30.13(PGND9) U30.21(AGND) ; also on sheet 1 2 10 11 12 13 14 15 16 17 18 19 20 21 22 23 24 25 26 27 28 29 30 31 32 33 34 35 36 37 38 39 40 41 42 43 44 45 46 47 48
V0P9_PLL: C95.1 C100.1 C105.1 L4.2 L5.2 L6.2 ; also on sheet 31
V0P87_CORE: C511.1P C512.1P C513.1P C514.1 C515.1 L29.2 R46.2 R111.1 R112.1 R332.2 R347.2 TP29.1(TP) ; also on sheet 13 14 16
V1P5: C111.1 L7.2 ; also on sheet 14 26 27 31
V2P5: C68.1 C82.1 C124.1 L1.1 L2.2 L9.2 R48.1 R86.1 R87.1 R88.1 R90.1 ; also on sheet 11 31
V3P3: C117.1 C391.2 C392.1 C403.2 C404.1 C405.1 C406.1 C407.1 C510.2 C526.1P C527.1P C528.1P C529.1 C530.1 FB6.1 J6.1 L3.2 L8.2 L30.2 R80.1 R81.1 R84.1 R85.1 R91.1 R92.1 R178.2 R179.2 R189.2 R193.2 R194.2 R195.2 R196.2 R197.2 R198.2 R199.2 R200.2 R201.2 R202.2 R203.2 R344.2 R345.2 R351.2 TP31.1(TP) U12.2(S2_PMOS) U14.E6(VCC_0) U14.F5(VCC_1) U14.J10(VCC_2) U14.K9(VCC_3) U29.22(VDRV) ; also on sheet 10 11 12 14 17 18 22 24 25 26 27 29 30 31 32 33 34 35 43 45
V3P3_BST: C523.1 U30.1(BST)
V3P3_CS2: U28.1(CS2) U30.17(CS)
V3P3_EN2: C500.1 R339.1 R340.2 U28.31(EN2)
V3P3_MMC: C408.1 C409.1 C410.1 J6.2 J8.4(VDD) R180.2 U12.4(D2_PMOS)
V3P3_PG: R338.1 U28.23(PG2) ; also on sheet 33
V3P3_PWM2: U28.28(PWM2) U30.15(PWM)
V3P3_SYNC2: U28.26(SYNC2) U30.19(SYNC)
V3P3_TIVA_LT: C491.1 C524.2 R318.2 R319.2 R320.2 R321.2 R325.1 R338.2 R339.2 R348.2 R349.2 U28.30(VDD33) U30.22(VDRV) ; also on sheet 1 2 19 20 21 28 29 31 37 38 39 40 42 43 44 46 47
V3P3_VDD2: C525.1 R348.1 U30.20(VDD)
V5P0: C395.1 C401.1 C402.1 U13.8(VCC) U15.24(VCC) ; also on sheet 18 25 29 30 31 33 38
V12P0_OCT: C502.1 C503.1 C504.1 C505.1 C506.1 C507.1 C517.1 C518.1 C519.1 C520.1 C521.1 C522.1 R313.2 R871.2 U29.2(VIN1) U29.14(VIN2) U30.2(VIN1) U30.14(VIN2)
V12P0_OCT_R: R871.1 ; also on sheet 28 29 30
VCCQ_MMC: C389.1 C390.1 C393.2 C394.1 C396.1 C397.1 C398.1 FB6.2 U14.C6(VCCQ_3) U14.M4(VCCQ_4) U14.N4(VCCQ_0) U14.P3(VCCQ_1) U14.P5(VCCQ_2)
VDD18: C493.1 R328.1 U28.14(VDD18)
VDD_CORE_CS1: U28.2(CS1) U29.17(CS)
VDD_CORE_PWM1: U28.29(PWM1) U29.15(PWM)
VDD_CORE_SYNC1: U28.27(SYNC1) U29.19(SYNC)
3P3_VORTN2: C501.2 R342.1 R343.2 U28.8(VORTN2)
3P3_VOSEN2: C501.1 R341.2 R342.2 U28.7(VOSEN2)
CORE_BST: C508.1 U29.1(BST)
CORE_EN1: C496.1 R330.2 R331.2 U28.32(EN1)
CORE_SENSE_MINUS: R336.2 ; also on sheet 13
CORE_SENSE_PLUS: R334.2 ; also on sheet 13
CORE_VDD1: C509.1 R344.1 U29.20(VDD)
CORE_VORTN1: C499.1 R335.1 U28.6(VORTN1)
CORE_VOSEN1: C498.1 R333.1 U28.5(VOSEN1)
DLM0_COMP_RES: R35.1 U1.P17(DLM0_COMP_RES)
DLM0_REF_CLK_100MHZ_N: U1.AE25(DLM0_REF_CLK_N) ; also on sheet 34
DLM0_REF_CLK_100MHZ_P: U1.AE24(DLM0_REF_CLK_P) ; also on sheet 34
DLM0_TX0_C_N: C61.1 U1.P25(DLM0_TXN<0>)
DLM0_TX0_C_P: C60.1 U1.N25(DLM0_TXP<0>)
DLM1_COMP_RES: R36.1 U1.U17(DLM1_COMP_RES)
DLM1_REF_CLK_100MHZ_N: U1.AF23(DLM1_REF_CLK_N) ; also on sheet 34
DLM1_REF_CLK_100MHZ_P: U1.AF24(DLM1_REF_CLK_P) ; also on sheet 34
DLM1_TX0_C_N: C63.2 U1.U25(DLM1_TXN<0>)
DLM1_TX0_C_P: C62.2 U1.T25(DLM1_TXP<0>)
DLM2_COMP_RES: R37.1 U1.Y17(DLM2_COMP_RES)
DLM2_REF_CLK_100MHZ_N: U1.AF22(DLM2_REF_CLK_N) ; also on sheet 34
DLM2_REF_CLK_100MHZ_P: U1.AE22(DLM2_REF_CLK_P) ; also on sheet 34
DLM2_RX0_N: U1.Y22(DLM2_RXN<0>) ; also on sheet 26
DLM2_RX0_P: U1.W22(DLM2_RXP<0>) ; also on sheet 26
DLM2_RX1_N: U1.AA23(DLM2_RXN<1>) ; also on sheet 27
DLM2_RX1_P: U1.Y23(DLM2_RXP<1>) ; also on sheet 27
DLM2_TX0_C_N: C65.1 U1.Y25(DLM2_TXN<0>)
DLM2_TX0_C_P: C64.1 U1.W25(DLM2_TXP<0>)
DLM2_TX0_N: C65.2 ; also on sheet 26
DLM2_TX0_P: C64.2 ; also on sheet 26
DLM2_TX1_C_N: C67.2 U1.AA26(DLM2_TXN<1>)
DLM2_TX1_C_P: C66.2 U1.Y26(DLM2_TXP<1>)
DLM2_TX1_N: C67.1 ; also on sheet 27
DLM2_TX1_P: C66.1 ; also on sheet 27
DLM3_COMP_RES: R38.1 U1.AC17(DLM3_COMP_RES)
DLM3_REF_CLK_100MHZ_N: U1.AF21(DLM3_REF_CLK_N) ; also on sheet 34
DLM3_REF_CLK_100MHZ_P: U1.AE21(DLM3_REF_CLK_P) ; also on sheet 34
DR_VTEMP: R315.2 U29.18(VTEMP) U30.18(VTEMP)
DUAL_RAIL_FAULT1#: R331.1 U29.23(FAULT#)
DUAL_RAIL_FAULT2#: R340.1 U30.23(FAULT#)
EMMC_BOOT_ISOLATE: R178.1 R181.2 U12.1(G1_NMOS) ; also on sheet 12
ENABLE_STAGE3: R330.1 ; also on sheet 33
ETHSW_GPIO: U1.V1(USB0_OVR_CRNT/GPIO_6) ; also on sheet 19
FLTR_OCT_DDR0_PLL_VDD_0P9V: C91.1 C92.1 C93.1 C94.1 L4.1 U1.H16(DDR_PLL_VDD)
FLTR_OCT_PLL_VDD_0P9V: C96.1 C97.1 C98.1 C99.1 L5.1 U1.AF10(PLL_VDD)
FLTR_OCT_SMI_VDD2P5V: C78.1 C79.1 C80.1 C81.1 L2.1 U1.AA11(VDD_SMI)
FLTR_OCT_SYS_PLL_VDD_0P9V: C101.1 C102.1 C103.1 C104.1 L6.1 U1.AF11(SYS_PLL_VDD)
FLTR_OCT_VDD_1P5V: C106.1 C107.1 C108.1 C109.1 C110.1 L7.1 U1.AA14(VDD_15_2) U1.W10(VDD_15_1)
FLTR_OCT_VDD_IO: C83.1 C84.1 C85.1 C86.1 C87.1 C88.1 C89.1 C90.1 L3.1 R113.2 U1.AB9(VDD_IO7) U1.AC4(VDD_IO8) U1.N8(VDD_IO1) U1.T5(VDD_IO2) U1.U8(VDD_IO3) U1.W4(VDD_IO4) U1.Y11(VDD_IO5) U1.Y13(VDD_IO6)
FLTR_VDD_OCT_EMMC_3P3V: C112.1 C113.1 C114.1 C115.1 C116.1 L8.1 U1.W8(VDD_EMMC1) U1.Y9(VDD_EMMC2)
FLTR_VDD_OCT_RGM_2P5V: C118.1 C119.1 C120.1 C121.1 C122.1 C123.1 L9.1 U1.AB15(VDD_RGM2) U1.AD13(VDD_RGM3) U1.AD17(VDD_RGM1)
IDT_INT: R89.1 U1.V2(USB0_VBUS_CTL/GPIO_7)
IDT_INT_REQ: R89.2 ; also on sheet 45
MEM_RESET_L: R187.1 ; also on sheet 22 32 43 44 45
MMC_CLK: J8.5(CLOCK) R193.1 U14.M6(CLK) U15.22(B1)
MMC_D0: J8.7(DAT0) R194.1 U14.A3(DAT0) U15.14(B9)
MMC_D1: J8.8(DAT1) R195.1 U14.A4(DAT1) U15.16(B7)
MMC_D2: J8.1(DAT2) R196.1 U14.A5(DAT2) U15.18(B5)
MMC_D3: J8.2(CD/DAT3) R197.1 U14.B2(DAT3) U15.13(B10)
MMC_D4: R198.1 U14.B3(DAT4) U15.15(B8)
MMC_D5: R199.1 U14.B4(DAT5) U15.17(B6)
MMC_D6: R200.1 U14.B5(DAT6) U15.19(B4)
MMC_D7: R201.1 U14.B6(DAT7) U15.20(B3)
MMC_FL_CMD: R186.2 R190.2 R202.1 U14.M5(CMD)
MMC_ISOLATE_L: R179.1 TP11.1 U12.3(G2_PMOS) U12.6(D1_NMOS) U13.1(OE_L) U15.23(\\~{OE})
MMC_RST_L: R187.2 U14.K5(RST_N)
MMC_SD_CMD: J8.3(CMD) R184.2 R188.2 R203.1
MMC_VDDIM: C399.2 C400.1 U14.C2(VDDIM)
OCT_EMMC_CLK: R98.2 U15.2(A1)
OCT_EMMC_CMD0: R103.2 R183.1 R188.1
OCT_EMMC_CMD1: R185.1 R190.1 U1.AD7(EMMC_CMD<1>)
OCT_EMMC_CMD2: TP5.1 U1.AC7(EMMC_CMD<2>)
OCT_EMMC_D0: R97.1 U15.10(A9)
OCT_EMMC_D1: R99.1 U15.8(A7)
OCT_EMMC_D2: R100.1 U15.6(A5)
OCT_EMMC_D3: R101.1 U15.11(A10)
OCT_EMMC_D4: R102.1 U15.9(A8)
OCT_EMMC_D5: R104.1 U15.7(A6)
OCT_EMMC_D6: R105.1 U15.5(A4)
OCT_EMMC_D7: R106.1 U15.4(A3)
OCT_RGM_COMP_DN: R48.2 U1.AC15(RGM_COMP_DN)
OCT_RGM_COMP_UP: R49.2 U1.AD15(RGM_COMP_UP)
OCT_SGMII_RX0_N: U1.U22(DLM1_RXN<0>) ; also on sheet 19
OCT_SGMII_RX0_P: U1.T22(DLM1_RXP<0>) ; also on sheet 19
OCT_SGMII_TX0_N: C63.1 ; also on sheet 19
OCT_SGMII_TX0_P: C62.1 ; also on sheet 19
OCT_SMI0_MDC: R87.2 U1.AE12(SMI0_MDC)
OCT_SMI0_MDIO: R86.2 U1.AE11(SMI0_MDIO)
OCT_SMI1_MDC: R90.2 U1.AD11(SMI1_MDC)
OCT_SMI1_MDIO: R88.2 U1.AC11(SMI1_MDIO)
OCT_SPI_CLK: R93.2 U1.AD10(SPI_CK) ; also on sheet 24
OCT_SPI_CS0_L: R91.2 U1.AB10(SPI_CS0_L) ; also on sheet 24
OCT_SPI_CS1_L: R92.2 U1.AC10(SPI_CS1_L)
OCT_SPI_MISO: U1.AD9(SPI_MISO) ; also on sheet 24
OCT_SPI_MOSI: U1.AE9(SPI_MOSI) ; also on sheet 24
OCT_TWS0_SCL: R79.1 ; also on sheet 45
OCT_TWS0_SDA: R78.1 ; also on sheet 45
OCT_TWS1_SCL: R83.2 R322.1 ; also on sheet 11 18 26 27 48
OCT_TWS1_SDA: R82.2 R323.1 ; also on sheet 11 18 26 27 48
OCT_UART0_CTS_L: U1.T1(UART0_CTS_L)
OCT_UART0_RTS_L: U1.T2(UART0_RTS_L) ; also on sheet 17
OCT_UART0_RXD: U1.P5(UART0_SIN) ; also on sheet 25
OCT_UART0_TXD: U1.P6(UART0_SOUT) ; also on sheet 25
OCT_UART1_CTS_L: U1.U1(UART1_CTS_L)
OCT_UART1_RTS_L: U1.U2(UART1_RTS_L) ; also on sheet 17
OCT_UART1_RXD: U1.T3(UART1_SIN)
OCT_UART1_TXD: U1.U3(UART1_SOUT)
OCT_USB0_DM: U1.H19(USB0_DM) ; also on sheet 22
OCT_USB0_DP: U1.J19(USB0_DP) ; also on sheet 22
OCT_USB0_REXT: R96.2 U1.G18(USB0_RESREF)
OCT_USB1_DM: U1.J21(USB1_DM) ; also on sheet 42
OCT_USB1_DP: U1.J20(USB1_DP) ; also on sheet 42
OCT_USB1_REXT: R95.2 U1.G19(USB1_RESREF)
OCT_USB1_SSRX_N: U1.L23(USB1_SSRX_M) ; also on sheet 42
OCT_USB1_SSRX_P: U1.M23(USB1_SSRX_P) ; also on sheet 42
OCT_USB1_SSTX_N: C77.1 ; also on sheet 42
OCT_USB1_SSTX_P: C76.1 ; also on sheet 42
OCT_USB_REF_CLK_N: U1.L20(USB_REF_CLK_N) ; also on sheet 35
OCT_USB_REF_CLK_P: U1.K20(USB_REF_CLK_P) ; also on sheet 35
PCIE0_RXN: R34.2 U1.P22(DLM0_RXN<0>) ; also on sheet 42
PCIE0_RXP: R34.1 U1.N22(DLM0_RXP<0>) ; also on sheet 42
PCIE0_TXN: C61.2 ; also on sheet 42
PCIE0_TXP: C60.2 ; also on sheet 42
PERST1_L: U1.N5(PERST1_L) ; also on sheet 26 27
PG_STAGE3: U28.24(PG1) ; also on sheet 33
PU_MP2951_CLK: R325.2 U28.22(CLK)
RGM0_REF_CLK: R47.1 U4.3(OUT)
RGM0_REF_CLK_125MHZ: R47.2 U1.AE15(RGM_REF_CLK)
RGM0_VDD_SELECT: R46.1 U1.AE13(RGM_VDD_SELECT)
RGMII_P6_RXCLK: U1.AD12(RGM_RXC) ; also on sheet 19
RGMII_P6_RXCTRL: U1.AC12(RGM_RXCTL) ; also on sheet 19
RGMII_P6_RXD0: U1.AC13(RGM_RXD<0>) ; also on sheet 19
RGMII_P6_RXD1: U1.AE14(RGM_RXD<1>) ; also on sheet 19
RGMII_P6_RXD2: U1.AC14(RGM_RXD<2>) ; also on sheet 19
RGMII_P6_RXD3: U1.AF15(RGM_RXD<3>) ; also on sheet 19
RGMII_P6_TXCLK: R43.2 ; also on sheet 19
RGMII_P6_TXCTRL: R44.2 ; also on sheet 19
RGMII_P6_TXD0: R39.2 ; also on sheet 19
RGMII_P6_TXD1: R40.2 ; also on sheet 19
RGMII_P6_TXD2: R41.2 ; also on sheet 19
RGMII_P6_TXD3: R42.2 ; also on sheet 19
SATA0_RX_N: U1.AC22(DLM3_RXN<0>) ; also on sheet 43
SATA0_RX_P: U1.AB22(DLM3_RXP<0>) ; also on sheet 43
SATA0_TX_N: U1.AC25(DLM3_TXN<0>) ; also on sheet 43
SATA0_TX_P: U1.AB25(DLM3_TXP<0>) ; also on sheet 43
SATA1_RX_N: U1.AD23(DLM3_RXN<1>) ; also on sheet 44
SATA1_RX_P: U1.AC23(DLM3_RXP<1>) ; also on sheet 44
SATA1_TX_N: U1.AD26(DLM3_TXN<1>) ; also on sheet 44
SATA1_TX_P: U1.AC26(DLM3_TXP<1>) ; also on sheet 44
SD_EMMC_SEL: J7.2 U13.5(EX) ; also on sheet 10
TIVA_I2C0_SCLK: J16.1 R320.1 R322.2 U28.20(SCL) ; also on sheet 19 37
TIVA_I2C0_SDA: J16.2 R319.1 R323.2 U28.19(SDA) ; also on sheet 19 37
TWS0_SCL: R79.2 R84.2 U1.L7(TWS0_SCL)
TWS0_SDA: R78.2 R80.2 U1.M6(TWS0_SDA)
TWS1_SCL: R83.1 R85.2 U1.M7(TWS1_SCL)
TWS1_SDA: R81.2 R82.1 U1.M8(TWS1_SDA)
USB0_VBUS: U1.H18(USB0_VBUS)
USB1_EN: R94.2
USB1_SSTX_N: C77.2 U1.L26(USB1_SSTX_M)
USB1_SSTX_P: C76.2 U1.M26(USB1_SSTX_P)
USB1_VBUS: U1.N18(USB1_VBUS)
USB1_VBUS_CTL: R94.1 U1.U7(USB1_VBUS_CTL/GPIO_5)
VRM_ADDR: C495.2 R326.2 R328.2 U28.12(ADDR)
VRM_ALERT#: J16.3 R318.1 U28.18(ALT#) ; also on sheet 37
VRM_VDIFF1: R327.1 U28.3(VDIFF1)
VRM_VFB1: R327.2 U28.4(VFB1)
VRM_WP: R321.1 R324.2 U28.21(WP)
VTEMP: C494.1 R315.1 R317.2 U28.10(VTEMP)
N17958563: R111.2 U1.AB13(SMI_VDD_SELECT)
N20718355: R98.1 U1.AF3(EMMC_CLK)
N20718378: R103.1 U1.AD8(EMMC_CMD<0>)
N20734740: R112.2 U1.AE8(IO_VDD_SELECT)
N21241417: R39.1 U1.AE16(RGM_TXD<0>)
N21241419: R42.1 U1.AE17(RGM_TXD<3>)
N21241421: R40.1 U1.AC16(RGM_TXD<1>)
N21241423: R41.1 U1.AF17(RGM_TXD<2>)
N21241465: R43.1 U1.AD16(RGM_TXC)
N21241467: R44.1 U1.AF16(RGM_TXCTL)
N21241730: C69.1 C70.1 L1.2 R45.2 U4.4(VCC)
N21241765: R45.1 U4.1(E/~{D})
N21504293: C492.1 R313.1 R314.2 U28.11(VINSEN)
N21528513: R349.1 U30.16(EN)
N21528724: C523.2 L30.1 R350.2 U30.3(SW1) U30.4(SW2)
N21532379: C531.1 R350.1
N21533857: R345.1 U29.16(EN)
N21533909: C508.2 L29.1 R346.2 U29.3(SW1) U29.4(SW2)
N21534139: C516.1 R346.1
N24744244: C497.1 R332.1 R333.2 R334.1
N24744252: C497.2 R335.2 R336.1 R337.2
N24747189: R329.2 U28.13(IREF)
N25950873: R97.2 U1.AF6(EMMC_DAT<0>)
N25950876: R99.2 U1.AE6(EMMC_DAT<1>)
N25950951: R101.2 U1.AC6(EMMC_DAT<3>)
N25950954: R100.2 U1.AD6(EMMC_DAT<2>)
N25951029: R102.2 U1.AF5(EMMC_DAT<4>)
N25951032: R104.2 U1.AE5(EMMC_DAT<5>)
N25951107: R106.2 U1.AF4(EMMC_DAT<7>)
N25951110: R105.2 U1.AD5(EMMC_DAT<6>)
N26037719: TP71.1 U1.N7(PERST2_L)
N28545311: R183.2 U13.2(A)
N28545378: R185.2 U13.3(B)
N28545449: R184.1 U13.7(C)
N28545451: R186.1 U13.6(D)
N29749420: TP1.1 U1.N6(PERST0_L)
N33640948: J7.1 R189.1
N33641110: J7.3 R191.2

Not connected (* = marked no-connect by the designer): U1 AA9(RSVD14) AA10(RSVD15) AA12(RSVD16) AA13(RSVD17) AA17(RSVD18) AA18(RSVD19) AB7(RSVD20) AB8(RSVD21) AF1(NC)* B1(RSVD3) F15(RSVD1) G15(RSVD2) J18(RSVD4) K22(USB0_SSRX_M) K25(USB0_SSTX_M) L22(USB0_SSRX_P) L25(USB0_SSTX_P) N17(RSVD5) P18(RSVD6) P23(DLM0_RXP<1>) P26(DLM0_TXP<1>) R17(RSVD7) R18(RSVD8) R23(DLM0_RXN<1>) R26(DLM0_TXN<1>) U6(USB1_OVR_CRNT/GPIO_4) U18(RSVD9) U23(DLM1_RXP<1>) U26(DLM1_TXP<1>) V17(RSVD10) V18(RSVD11) V23(DLM1_RXN<1>) V26(DLM1_TXN<1>) W16(RSVD12) Y18(RSVD13); U14 A1(NC_0)* A2(NC_1)* A6(RFU_0)* A7(RFU_1)* A8(NC_2)* A9(NC_3)* A10(NC_4)* A11(NC_5)* A12(NC_6)* A13(NC_7)* A14(NC_8)* B1(NC_9)* B7(NC_10)* B8(NC_11)* B9(NC_12)* B10(NC_13)* B11(NC_14)* B12(NC_15)* B13(NC_16)* B14(NC_17)* C1(NC_18)* C3(NC_19)* C5(RFU_3)* C7(NC_20)* C8(NC_21)* C9(NC_22)* C10(NC_23)* C11(NC_24)* C12(NC_25)* C13(NC_26)* C14(NC_27)* D1(NC_28)* D2(NC_29)* D3(NC_30)* D4(NC_31)* D12(NC_32)* D13(NC_33)* D14(NC_34)* E1(NC_35)* E2(NC_36)* E3(NC_37)* E5(RFU_2)* E8(RFU_5)* E9(RFU_6)* E10(RFU_7)* E12(NC_38)* E13(NC_39)* E14(NC_40)* F1(NC_41)* F2(NC_42)* F3(NC_43)* F10(RFU_8)* F12(NC_44)* F13(NC_45)* F14(NC_46)* G1(NC_47)* G2(NC_48)* G3(NC_49)* G10(RFU_9)* G12(NC_50)* G13(NC_51)* G14(NC_52)* H1(NC_53)* H2(NC_54)* H3(NC_55)* H5(RFU_4)* H12(NC_56)* H13(NC_57)* H14(NC_58)* J1(NC_59)* J2(NC_60)* J3(NC_61)* J5(RFU_10)* J12(NC_62)* J13(NC_63)* J14(NC_64)* K1(NC_65)* K2(NC_66)* K3(NC_67)* K6(RFU_11)* K7(RFU_12)* K10(RFU_13)* K12(NC_68)* K13(NC_69)* K14(NC_70)* L1(NC_71)* L2(NC_72)* L3(NC_73)* L12(NC_74)* L13(NC_75)* L14(NC_76)* M1(NC_77)* M2(NC_78)* M3(NC_79)* M7(NC_80)* M8(NC_81)* M9(NC_82)* M10(NC_83)* M11(NC_84)* M12(NC_85)* M13(NC_86)* M14(NC_87)* N1(NC_88)* N3(NC_89)* N6(NC_90)* N7(NC_91)* N8(NC_92)* N9(NC_93)* N10(NC_94)* N11(NC_95)* N12(NC_96)* N13(NC_97)* N14(NC_98)* P1(NC_99)* P2(NC_100)* P7(RFU_14)* P8(NC_101)* P9(NC_102)* P10(RFU_15)* P11(NC_103)* P12(NC_104)* P13(NC_105)* P14(NC_106)*; U15 1(NC)* 3(A2)* 21(B2)*; U28 9(NC1)* 16(NC2)* 17(NC3)*

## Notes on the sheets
sheet 49
- eMMC Flash
- HIGH => eMMC Flash Boot
  LOW => SD Card Boot
sheet 50
- PCIE TO SDR Connector
- PCIE TO SDR Connector
- HCSL - 100MHz
- dlm1 sgmii
- 100mhz
- [2 x 1 XFI]
- MINI PCIE
- MINI PCIE
- connect to mini-pcie connector0 and
  mini-pcie connector1
- config to SATA
- PEM2
- [1 x 1 PCIE ]
- HCSL - 100MHz
- DLM Configuration
- OUTPUT
- INPUT
- DLM#
- MAC
- OCT IOT/ROUTER Gateway
- DLM0
- PEM0
- 1x1 PCIe
- DLM1
- BGX0
- 1x1 SGMII
- DLM2
- PEM1
- 2x1 PCIE
- DLM3
- SATA0-1
- 2X1 SATA
- INSTALL=>VDD_RGM = 2.5V
sheet 51
- Supply Voltage for the On-Chip PLLs
- Place close to the filter
- Place close to the device
- SMI_VDD_SELECT & IO_VDD_SELECT
- Place close to the device
- Place close to the filter
- Selects VDD level for SMI/MDIO:
  3.3V = NC
  2.5V = 1K pull-up to VDD
- Place close to
  the device
- Place close to the filter
- Place close to
  the device
- Place close to the filter
- Place close to
  the device
- Place close to the filter
- Place close to
  the device
- Place close to the filter
- Place close to
  the device
- Place close to the filter
- Place close to
  the device
sheet 52
- PMBus Address - (20)h
- Connect to VDD_SEN+
- Connect to VDD_SEN-
- Remote sense
sheet 53
- TWSI1 = Daughter Card
- UART1 = Daughter Card
- USB0 as USB2.0 to TIVA
- USB1 as USB3.0 to SDR
- to SDR connector
sheet 54
- use large copper shape
- use large copper shape
- R1218 JUMPER
- use large copper shape
- 3.3V
- recalculator the resistor
